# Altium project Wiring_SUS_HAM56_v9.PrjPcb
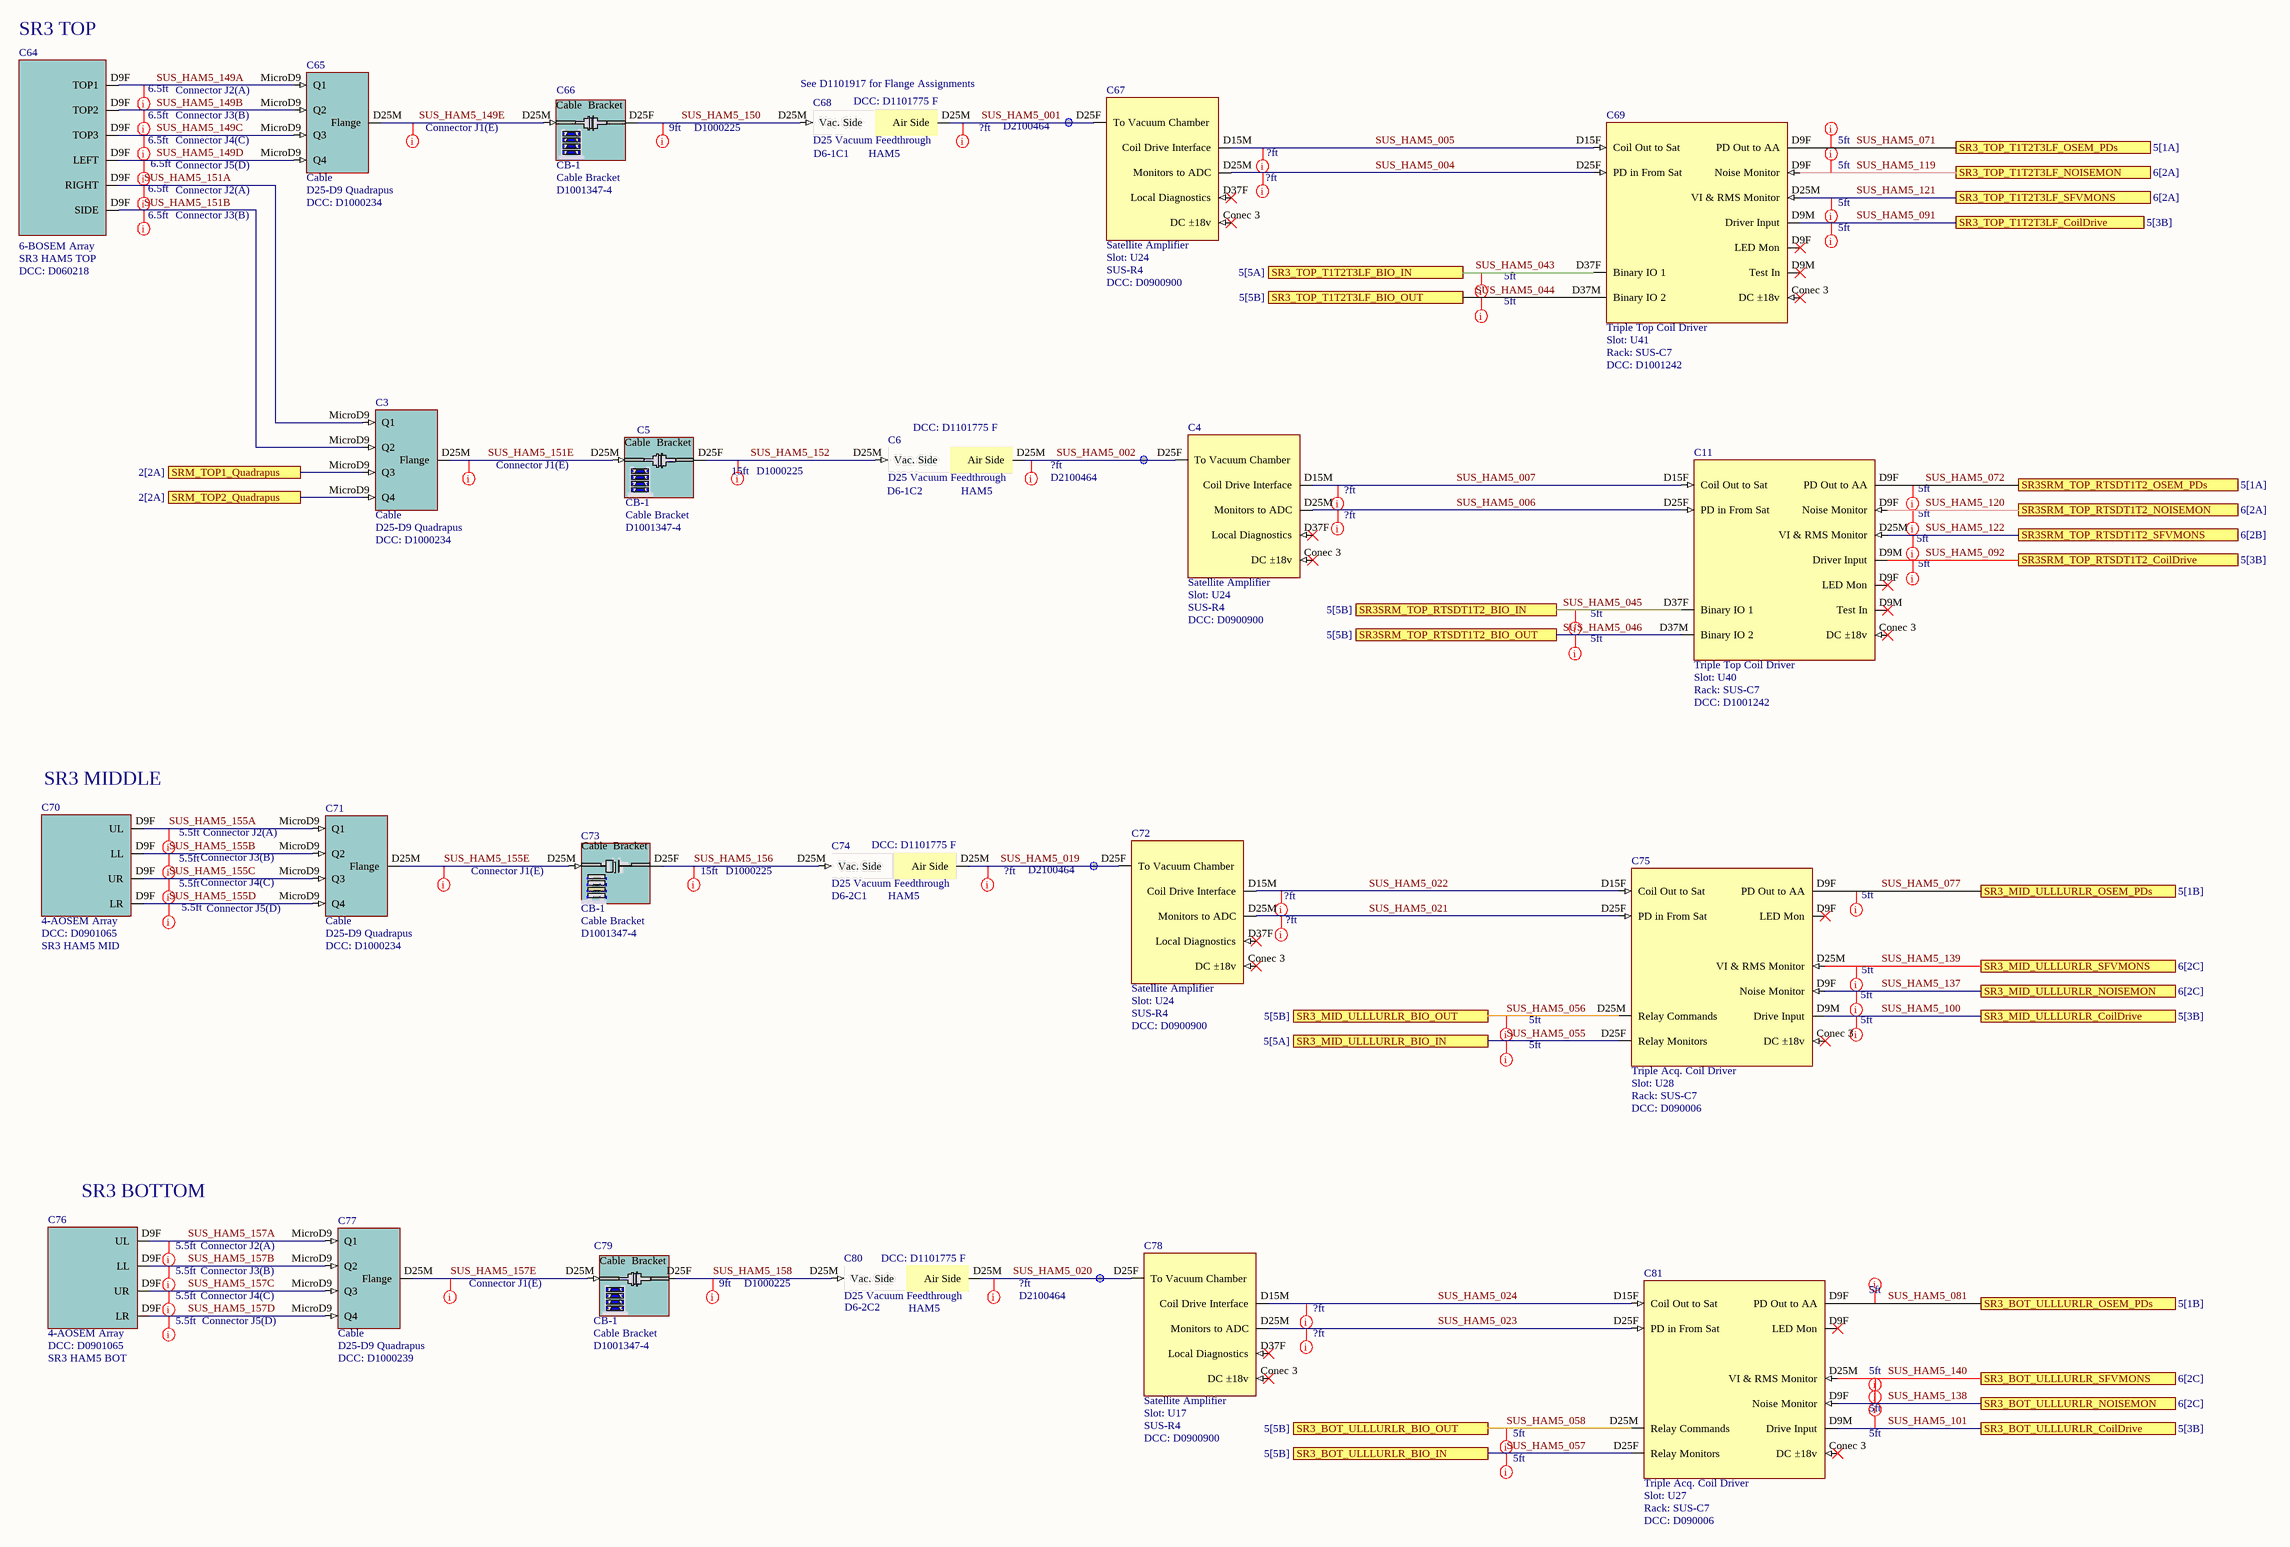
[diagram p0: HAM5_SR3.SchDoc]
8 sheets, 119 parts. Net scope: flat (ports and power ports of the same name join across sheets).
Sheets:
  HAM5_SR3.SchDoc
  HAM5_SRM.SchDoc
  HAM5_OFI_ZM6.SchDoc
  HAM6_OUT_SUS.SchDoc
  SUSH56_ADC_DAC.SchDoc
  SUSAUXH56_ADC_DAC.SchDoc
  RACK_SUS_R4.SchDoc
  RACK_SUS_C7_C8.SchDoc

## Sheet HAM5_SR3.SchDoc: HAM5 SR3 OSEMs to Drivers
size C; Engineer: L. Sanchez; Organization: LIGO Laboratory; Address1: California Institute of Technology; Address2: Massachusetts Institute of Technology; DocumentNumber: D1002740; Revision: v9; SheetNumber: 1; SheetTotal: 8

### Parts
C3  Cable  value D25-D9 Quadrapus  DCC: D1000234
C4  Satellite Amplifier  Slot: U24  Rack: SUS-R4  DCC: D0900900
C5  Slot: CB-1  DCC: D1001347-4  (hidden comment: Cable Bracket)
C6  D25 Vacuum Feedthrough  DCC: D1101775 F  Feedthrough: D6-1C2  Chamber: HAM5
C11  Triple Top Coil Driver  Slot: U40  Rack: SUS-C7  DCC: D1001242
C64  6-BOSEM Array  Parameter 1: SR3 HAM5 TOP  DCC: D060218
C65  Cable  value D25-D9 Quadrapus  DCC: D1000234
C66  Slot: CB-1  DCC: D1001347-4  (hidden comment: Cable Bracket)
C67  Satellite Amplifier  Slot: U24  Rack: SUS-R4  DCC: D0900900
C68  D25 Vacuum Feedthrough  DCC: D1101775 F  Feedthrough: D6-1C1  Chamber: HAM5
C69  Triple Top Coil Driver  Slot: U41  Rack: SUS-C7  DCC: D1001242
C70  4-AOSEM Array  DCC: D0901065  Parameter: SR3 HAM5 MID
C71  Cable  value D25-D9 Quadrapus  DCC: D1000234
C72  Satellite Amplifier  Slot: U24  Rack: SUS-R4  DCC: D0900900
C73  Slot: CB-1  DCC: D1001347-4  (hidden comment: Cable Bracket)
C74  D25 Vacuum Feedthrough  DCC: D1101775 F  Feedthrough: D6-2C1  Chamber: HAM5
C75  Triple Acq. Coil Driver  Slot: U28  Rack: SUS-C7  DCC: D090006
C76  4-AOSEM Array  DCC: D0901065  Parameter: SR3 HAM5 BOT
C77  Cable  value D25-D9 Quadrapus  DCC: D1000239
C78  Satellite Amplifier  Slot: U17  Rack: SUS-R4  DCC: D0900900
C79  Slot: CB-1  DCC: D1001347-4  (hidden comment: Cable Bracket)
C80  D25 Vacuum Feedthrough  DCC: D1101775 F  Feedthrough: D6-2C2  Chamber: HAM5
C81  Triple Acq. Coil Driver  Slot: U27  Rack: SUS-C7  DCC: D090006

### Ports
SR3_BOT_ULLLURLR_BIO_IN (see 5[5B]), SR3_BOT_ULLLURLR_BIO_OUT (see 5[5B]), SR3_BOT_ULLLURLR_CoilDrive (see 5[3B]), SR3_BOT_ULLLURLR_NOISEMON (see 6[2C]), SR3_BOT_ULLLURLR_OSEM_PDs (see 5[1B]), SR3_BOT_ULLLURLR_SFVMONS (see 6[2C]), SR3_MID_ULLLURLR_BIO_IN (see 5[5A]), SR3_MID_ULLLURLR_BIO_OUT (see 5[5B]), SR3_MID_ULLLURLR_CoilDrive (see 5[3B]), SR3_MID_ULLLURLR_NOISEMON (see 6[2C]), SR3_MID_ULLLURLR_OSEM_PDs (see 5[1B]), SR3_MID_ULLLURLR_SFVMONS (see 6[2C]), SR3_TOP_T1T2T3LF_BIO_IN (see 5[5A]), SR3_TOP_T1T2T3LF_BIO_OUT (see 5[5B]), SR3_TOP_T1T2T3LF_CoilDrive (see 5[3B]), SR3_TOP_T1T2T3LF_NOISEMON (see 6[2A]), SR3_TOP_T1T2T3LF_OSEM_PDs (see 5[1A]), SR3_TOP_T1T2T3LF_SFVMONS (see 6[2A]), SR3SRM_TOP_RTSDT1T2_BIO_IN (see 5[5B]), SR3SRM_TOP_RTSDT1T2_BIO_OUT (see 5[5B]), SR3SRM_TOP_RTSDT1T2_CoilDrive (see 5[3B]), SR3SRM_TOP_RTSDT1T2_NOISEMON (see 6[2A]), SR3SRM_TOP_RTSDT1T2_OSEM_PDs (see 5[1A]), SR3SRM_TOP_RTSDT1T2_SFVMONS (see 6[2B]), SRM_TOP1_Quadrapus (see 2[2A]), SRM_TOP2_Quadrapus (see 2[2A])

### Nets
SUS_HAM5_001: C67.D25F(To_Vacuum_Chamber) C68.D25M(Air_Side)
SUS_HAM5_002: C4.D25F(To_Vacuum_Chamber) C6.D25M(Air_Side)
SUS_HAM5_004: C67.D25M(Monitors_to_ADC) C69.D25F(PD_in_From_Sat)
SUS_HAM5_005: C67.D15M(Coil_Drive_Interface) C69.D15F(Coil_Out_to_Sat)
SUS_HAM5_006: C4.D25M(Monitors_to_ADC) C11.D25F(PD_in_From_Sat)
SUS_HAM5_007: C4.D15M(Coil_Drive_Interface) C11.D15F(Coil_Out_to_Sat)
SUS_HAM5_019: C72.D25F(To_Vacuum_Chamber) C74.D25M(Air_Side)
SUS_HAM5_020: C78.D25F(To_Vacuum_Chamber) C80.D25M(Air_Side)
SUS_HAM5_021: C72.D25M(Monitors_to_ADC) C75.D25F(PD_in_From_Sat)
SUS_HAM5_022: C72.D15M(Coil_Drive_Interface) C75.D15F(Coil_Out_to_Sat)
SUS_HAM5_023: C78.D25M(Monitors_to_ADC) C81.D25F(PD_in_From_Sat)
SUS_HAM5_024: C78.D15M(Coil_Drive_Interface) C81.D15F(Coil_Out_to_Sat)
SUS_HAM5_043: C69.D37F(Binary_IO_1) ; port SR3_TOP_T1T2T3LF_BIO_IN
SUS_HAM5_044: C69.D37M(Binary_IO_2) ; port SR3_TOP_T1T2T3LF_BIO_OUT
SUS_HAM5_045: C11.D37F(Binary_IO_1) ; port SR3SRM_TOP_RTSDT1T2_BIO_IN
SUS_HAM5_046: C11.D37M(Binary_IO_2) ; port SR3SRM_TOP_RTSDT1T2_BIO_OUT
SUS_HAM5_055: C75.D25F(Relay_Monitors) ; port SR3_MID_ULLLURLR_BIO_IN
SUS_HAM5_056: C75.D25M(Relay_Commands) ; port SR3_MID_ULLLURLR_BIO_OUT
SUS_HAM5_057: C81.D25F(Relay_Monitors) ; port SR3_BOT_ULLLURLR_BIO_IN
SUS_HAM5_058: C81.D25M(Relay_Commands) ; port SR3_BOT_ULLLURLR_BIO_OUT
SUS_HAM5_071: C69.D9F(PD_Out_to_AA) ; port SR3_TOP_T1T2T3LF_OSEM_PDs
SUS_HAM5_072: C11.D9F(PD_Out_to_AA) ; port SR3SRM_TOP_RTSDT1T2_OSEM_PDs
SUS_HAM5_077: C75.D9F(PD_Out_to_AA) ; port SR3_MID_ULLLURLR_OSEM_PDs
SUS_HAM5_081: C81.D9F(PD_Out_to_AA) ; port SR3_BOT_ULLLURLR_OSEM_PDs
SUS_HAM5_091: C69.D9M(Test_In) ; port SR3_TOP_T1T2T3LF_CoilDrive
SUS_HAM5_092: C11.D9M(Test_In) ; port SR3SRM_TOP_RTSDT1T2_CoilDrive
SUS_HAM5_100: C75.D9M(Drive_Input) ; port SR3_MID_ULLLURLR_CoilDrive
SUS_HAM5_101: C81.D9M(Drive_Input) ; port SR3_BOT_ULLLURLR_CoilDrive
SUS_HAM5_119: C69.D9F(Noise_Monitor) ; port SR3_TOP_T1T2T3LF_NOISEMON
SUS_HAM5_120: C11.D9F(Noise_Monitor) ; port SR3SRM_TOP_RTSDT1T2_NOISEMON
SUS_HAM5_121: C69.D25M(VI_&_RMS_Monitor) ; port SR3_TOP_T1T2T3LF_SFVMONS
SUS_HAM5_122: C11.D25M(VI_&_RMS_Monitor) ; port SR3SRM_TOP_RTSDT1T2_SFVMONS
SUS_HAM5_137: C75.D9F(Noise_Monitor) ; port SR3_MID_ULLLURLR_NOISEMON
SUS_HAM5_138: C81.D9F(Noise_Monitor) ; port SR3_BOT_ULLLURLR_NOISEMON
SUS_HAM5_139: C75.D25M(VI_&_RMS_Monitor) ; port SR3_MID_ULLLURLR_SFVMONS
SUS_HAM5_140: C81.D25M(VI_&_RMS_Monitor) ; port SR3_BOT_ULLLURLR_SFVMONS
SUS_HAM5_149A: C64.D9F(TOP1) C65.MicroD9(Q1)
SUS_HAM5_149B: C64.D9F(TOP2) C65.MicroD9(Q2)
SUS_HAM5_149C: C64.D9F(TOP3) C65.MicroD9(Q3)
SUS_HAM5_149D: C64.D9F(LEFT) C65.MicroD9(Q4)
SUS_HAM5_149E: C65.D25M(Flange) C66.D25M
SUS_HAM5_150: C66.D25F C68.D25M(Vac._Side)
SUS_HAM5_151A: C3.MicroD9(Q1) C64.D9F(RIGHT)
SUS_HAM5_151B: C3.MicroD9(Q2) C64.D9F(SIDE)
SUS_HAM5_151C: C3.MicroD9(Q3) ; port SRM_TOP1_Quadrapus
SUS_HAM5_151D: C3.MicroD9(Q4) ; port SRM_TOP2_Quadrapus
SUS_HAM5_151E: C3.D25M(Flange) C5.D25M
SUS_HAM5_152: C5.D25F C6.D25M(Vac._Side)
SUS_HAM5_155A: C70.D9F(UL) C71.MicroD9(Q1)
SUS_HAM5_155B: C70.D9F(LL) C71.MicroD9(Q2)
SUS_HAM5_155C: C70.D9F(UR) C71.MicroD9(Q3)
SUS_HAM5_155D: C70.D9F(LR) C71.MicroD9(Q4)
SUS_HAM5_155E: C71.D25M(Flange) C73.D25M
SUS_HAM5_156: C73.D25F C74.D25M(Vac._Side)
SUS_HAM5_157A: C76.D9F(UL) C77.MicroD9(Q1)
SUS_HAM5_157B: C76.D9F(LL) C77.MicroD9(Q2)
SUS_HAM5_157C: C76.D9F(UR) C77.MicroD9(Q3)
SUS_HAM5_157D: C76.D9F(LR) C77.MicroD9(Q4)
SUS_HAM5_157E: C77.D25M(Flange) C79.D25M
SUS_HAM5_158: C79.D25F C80.D25M(Vac._Side)

Not connected (* = marked no-connect by the designer): C4 Conec 3(DC_±18v)* D37F(Local_Diagnostics)*; C11 Conec 3(DC_±18v)*; C67 Conec 3(DC_±18v)* D37F(Local_Diagnostics)*; C69 Conec 3(DC_±18v)*; C72 Conec 3(DC_±18v)* D37F(Local_Diagnostics)*; C75 Conec 3(DC_±18v)*; C78 Conec 3(DC_±18v)* D37F(Local_Diagnostics)*; C81 Conec 3(DC_±18v)*

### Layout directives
Length: 5ft; DCC: Dxxxxxxx: SUS_HAM5_043, SUS_HAM5_044, SUS_HAM5_045, SUS_HAM5_046, SUS_HAM5_055, SUS_HAM5_056, SUS_HAM5_057, SUS_HAM5_058, SUS_HAM5_071, SUS_HAM5_072, SUS_HAM5_077, SUS_HAM5_081, SUS_HAM5_091, SUS_HAM5_092, SUS_HAM5_100, SUS_HAM5_101, SUS_HAM5_119, SUS_HAM5_120, SUS_HAM5_121, SUS_HAM5_122, SUS_HAM5_137, SUS_HAM5_138, SUS_HAM5_139, SUS_HAM5_140
Length: ?ft; DCC: Dxxxxxxx: SUS_HAM5_004, SUS_HAM5_005, SUS_HAM5_006, SUS_HAM5_007, SUS_HAM5_021, SUS_HAM5_022, SUS_HAM5_023, SUS_HAM5_024
Length: 6.5ft; DCC: Connector J1(E): SUS_HAM5_149E, SUS_HAM5_151E
Length: 15ft; DCC: D1000225: SUS_HAM5_152, SUS_HAM5_156
Length: ?ft; DCC: D2100464: SUS_HAM5_001, SUS_HAM5_002, SUS_HAM5_019, SUS_HAM5_020
Length: 6.5ft; DCC: Connector J2(A): SUS_HAM5_149A, SUS_HAM5_151A
Length: 6.5ft; DCC: Connector J3(B): SUS_HAM5_149B, SUS_HAM5_151B
Length: 9ft; DCC: D1000225: SUS_HAM5_150, SUS_HAM5_158
Length: 6.5ft; DCC: Connector J4(C): SUS_HAM5_149C
Length: 6.5ft; DCC: Connector J5(D): SUS_HAM5_149D
Length: 5ft; DCC: Connector J1(E): SUS_HAM5_157E
Length: 5.5ft; DCC: Connector J1(E): SUS_HAM5_155E
Length: 5.5ft; DCC: Connector J2(A): SUS_HAM5_155A, SUS_HAM5_157A
Length: 5.5ft; DCC: Connector J3(B): SUS_HAM5_155B, SUS_HAM5_157B
Length: 5.5ft; DCC: Connector J4(C): SUS_HAM5_155C, SUS_HAM5_157C
Length: 5.5ft; DCC: Connector J5(D): SUS_HAM5_155D, SUS_HAM5_157D

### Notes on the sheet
- (near C64) SR3 TOP
- (near C68) See D1101917 for Flange Assignments
- (near C70) SR3 MIDDLE
- (near C76) SR3 BOTTOM

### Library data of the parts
C3 C65 C71 C77 = Flange: Rack: SUS-R?; Serial: Sxxxxxxx; Slot: U?; System: SUS
C4 C67 C72 C78 = Satellite Amplifier: System: SUS; Serial: Sxxxxxxx
C5 = Cable Bracket 4 1-4: Rack: SUS-R?; Serial: Sxxxxxxx; System: SUS
C6 C68 C74 C80 = VacFeedD25: Serial: Sxxxxxxx; System: ISC; Rack: R?; Slot: U?
C11 C69 = Triple Top CD: System: SUS; Serial: Sxxxxxxx
C64 = 6-BOSEM Array HAM: Serial: Sxxxxxxx; System: SUS; Slot: U?; Rack: SUS-R?
C66 = Cable Bracket 3 1-4: Rack: SUS-R?; Serial: Sxxxxxxx; System: SUS
C70 C76 = 4-BOSEM Array: Rack: SUS-R?; Serial: Sxxxxxxx; Slot: U?; System: SUS
C73 = Cable Bracket 2 1-4: Rack: SUS-R?; Serial: Sxxxxxxx; System: SUS
C75 C81 = Triple Acquisition Coil Driver: System: SUS; Serial: Sxxxxxxx
C79 = Cable Bracket 1 1-4: Rack: SUS-R?; Serial: Sxxxxxxx; System: SUS

## Sheet HAM5_SRM.SchDoc: HAM5 SRM OSEMs to Drivers
size C; Engineer: L. Sanchez; Organization: LIGO Laboratory; Address1: California Institute of Technology; Address2: Massachusetts Institute of Technology; DocumentNumber: D1002740; Revision: v9; SheetNumber: 2; SheetTotal: 8
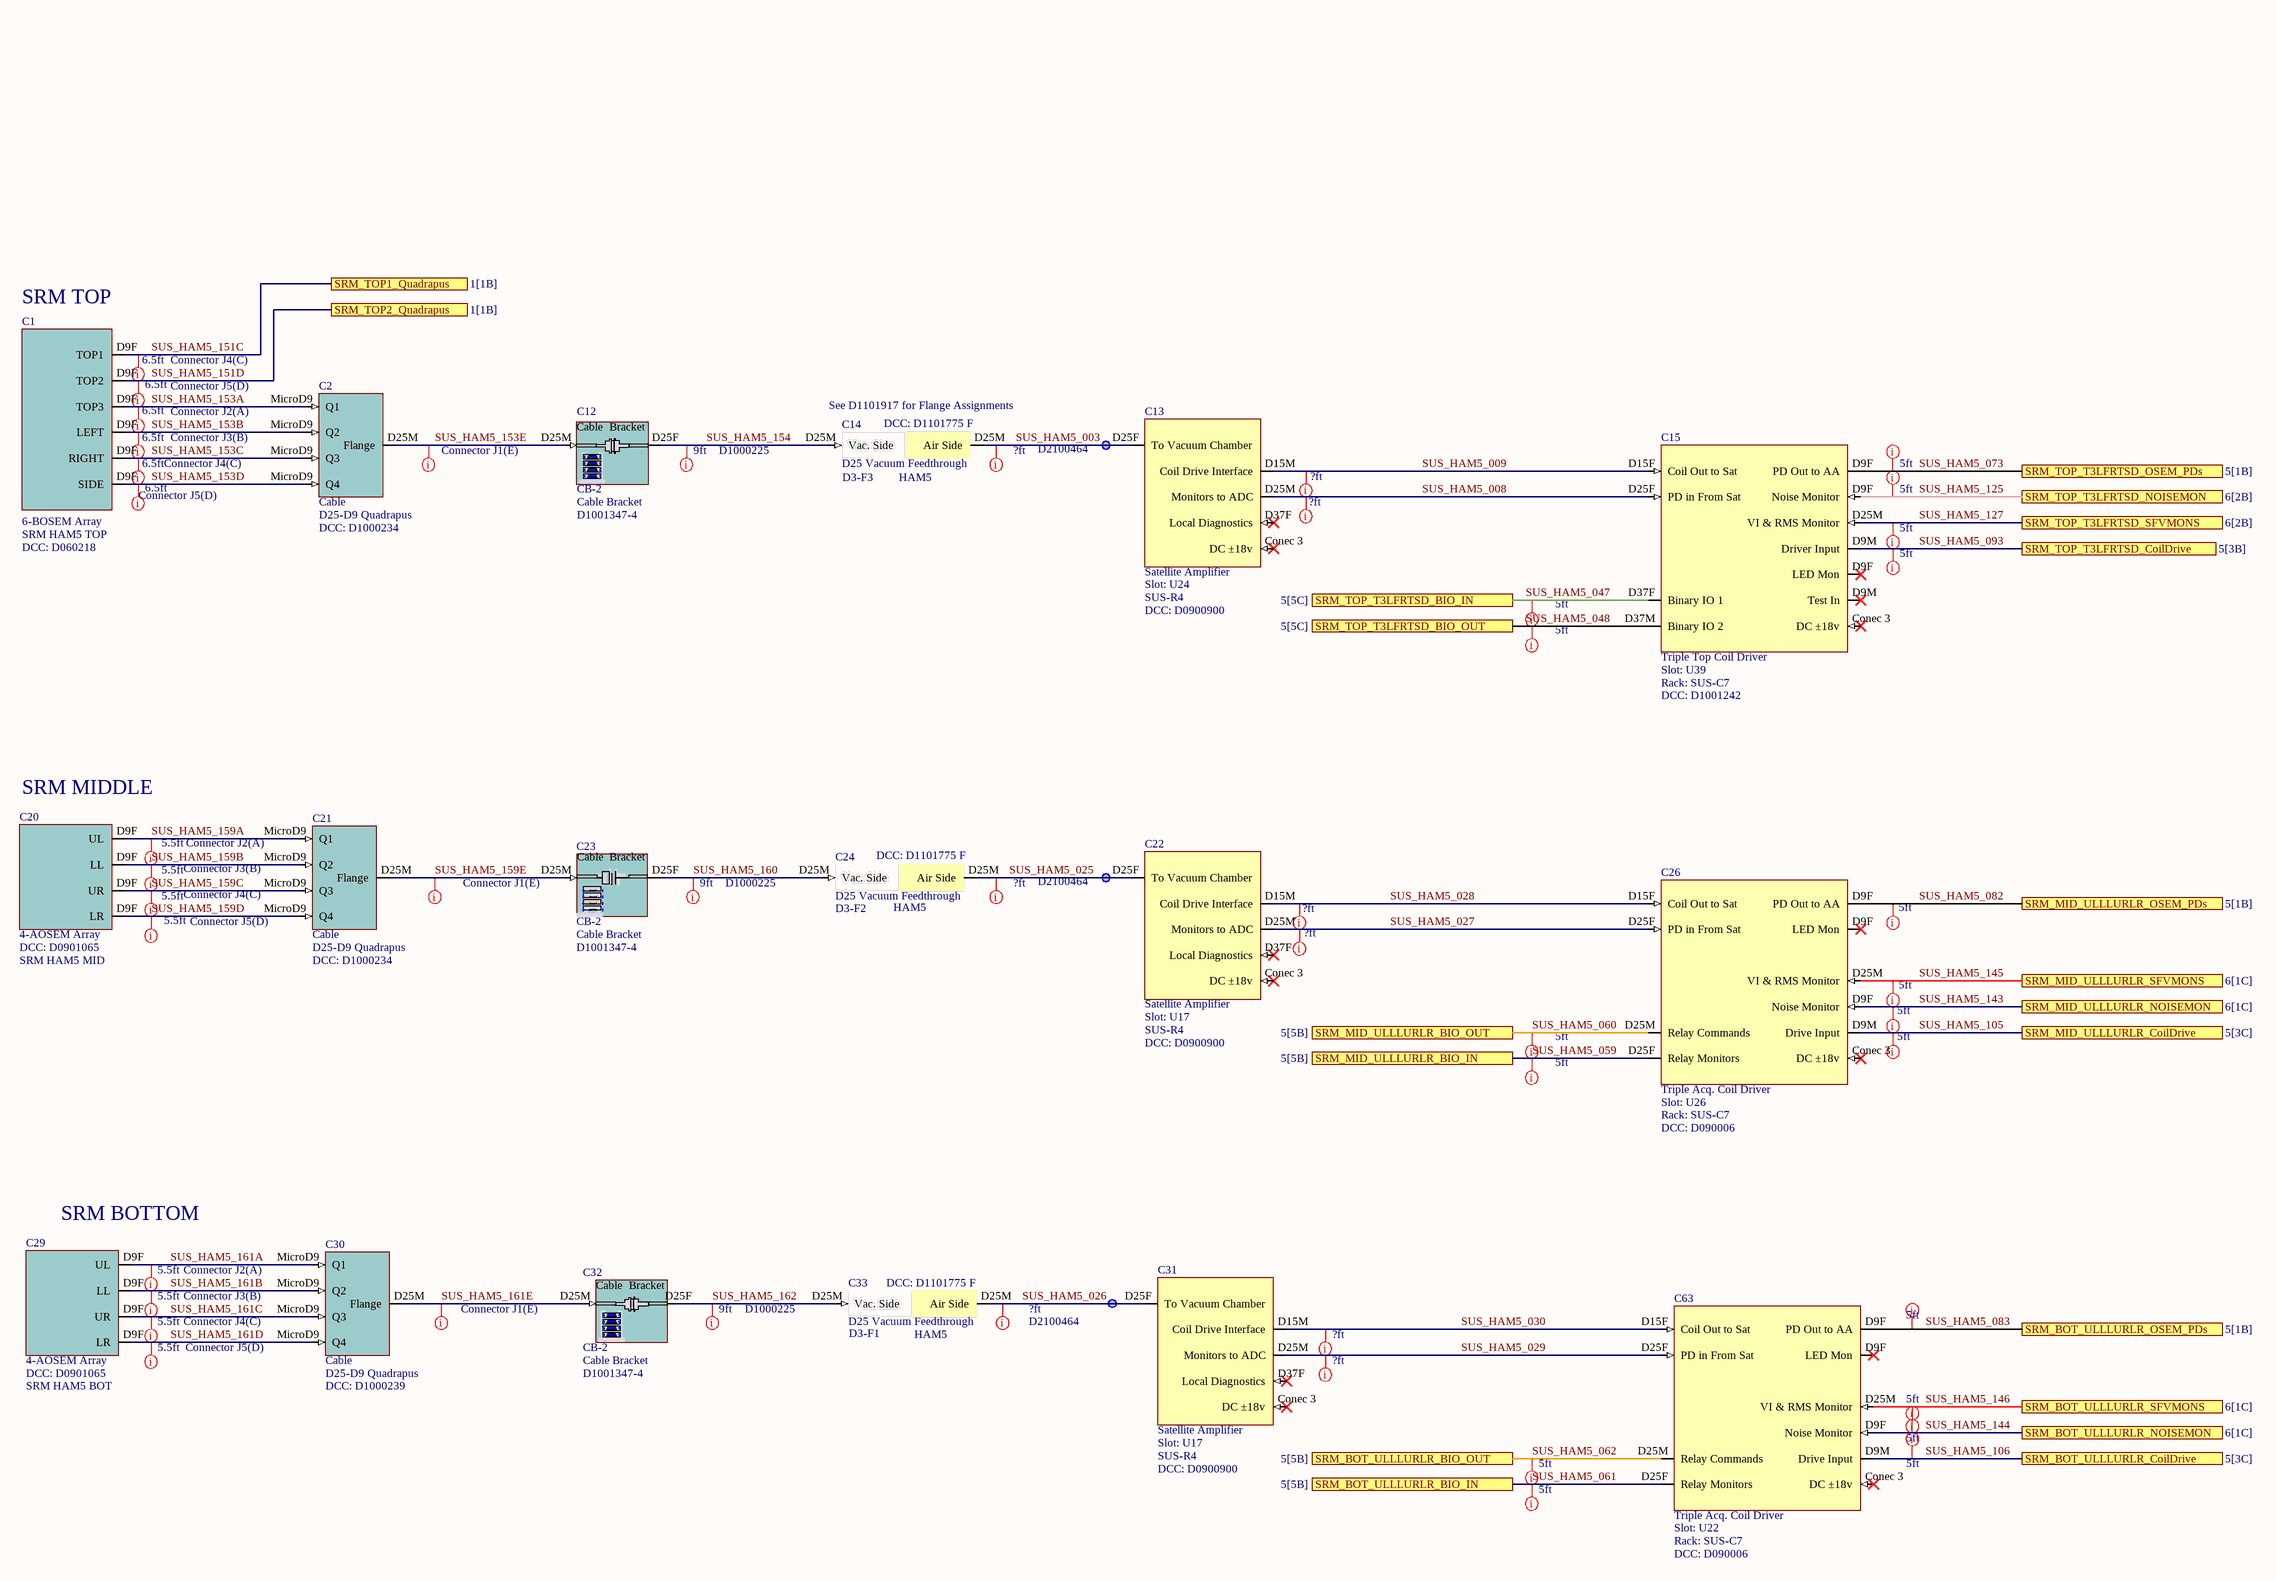
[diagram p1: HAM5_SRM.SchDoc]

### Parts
C1  6-BOSEM Array  Parameter 1: SRM HAM5 TOP  DCC: D060218
C2  Cable  value D25-D9 Quadrapus  DCC: D1000234
C12  Slot: CB-2  DCC: D1001347-4  (hidden comment: Cable Bracket)
C13  Satellite Amplifier  Slot: U24  Rack: SUS-R4  DCC: D0900900
C14  D25 Vacuum Feedthrough  DCC: D1101775 F  Feedthrough: D3-F3  Chamber: HAM5
C15  Triple Top Coil Driver  Slot: U39  Rack: SUS-C7  DCC: D1001242
C20  4-AOSEM Array  DCC: D0901065  Parameter: SRM HAM5 MID
C21  Cable  value D25-D9 Quadrapus  DCC: D1000234
C22  Satellite Amplifier  Slot: U17  Rack: SUS-R4  DCC: D0900900
C23  Slot: CB-2  DCC: D1001347-4  (hidden comment: Cable Bracket)
C24  D25 Vacuum Feedthrough  DCC: D1101775 F  Feedthrough: D3-F2  Chamber: HAM5
C26  Triple Acq. Coil Driver  Slot: U26  Rack: SUS-C7  DCC: D090006
C29  4-AOSEM Array  DCC: D0901065  Parameter: SRM HAM5 BOT
C30  Cable  value D25-D9 Quadrapus  DCC: D1000239
C31  Satellite Amplifier  Slot: U17  Rack: SUS-R4  DCC: D0900900
C32  Slot: CB-2  DCC: D1001347-4  (hidden comment: Cable Bracket)
C33  D25 Vacuum Feedthrough  DCC: D1101775 F  Feedthrough: D3-F1  Chamber: HAM5
C63  Triple Acq. Coil Driver  Slot: U22  Rack: SUS-C7  DCC: D090006

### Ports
SRM_BOT_ULLLURLR_BIO_IN (see 5[5B]), SRM_BOT_ULLLURLR_BIO_OUT (see 5[5B]), SRM_BOT_ULLLURLR_CoilDrive (see 5[3C]), SRM_BOT_ULLLURLR_NOISEMON (see 6[1C]), SRM_BOT_ULLLURLR_OSEM_PDs (see 5[1B]), SRM_BOT_ULLLURLR_SFVMONS (see 6[1C]), SRM_MID_ULLLURLR_BIO_IN (see 5[5B]), SRM_MID_ULLLURLR_BIO_OUT (see 5[5B]), SRM_MID_ULLLURLR_CoilDrive (see 5[3C]), SRM_MID_ULLLURLR_NOISEMON (see 6[1C]), SRM_MID_ULLLURLR_OSEM_PDs (see 5[1B]), SRM_MID_ULLLURLR_SFVMONS (see 6[1C]), SRM_TOP1_Quadrapus (see 1[1B]), SRM_TOP2_Quadrapus (see 1[1B]), SRM_TOP_T3LFRTSD_BIO_IN (see 5[5C]), SRM_TOP_T3LFRTSD_BIO_OUT (see 5[5C]), SRM_TOP_T3LFRTSD_CoilDrive (see 5[3B]), SRM_TOP_T3LFRTSD_NOISEMON (see 6[2B]), SRM_TOP_T3LFRTSD_OSEM_PDs (see 5[1B]), SRM_TOP_T3LFRTSD_SFVMONS (see 6[2B])

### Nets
SUS_HAM5_003: C13.D25F(To_Vacuum_Chamber) C14.D25M(Air_Side)
SUS_HAM5_008: C13.D25M(Monitors_to_ADC) C15.D25F(PD_in_From_Sat)
SUS_HAM5_009: C13.D15M(Coil_Drive_Interface) C15.D15F(Coil_Out_to_Sat)
SUS_HAM5_025: C22.D25F(To_Vacuum_Chamber) C24.D25M(Air_Side)
SUS_HAM5_026: C31.D25F(To_Vacuum_Chamber) C33.D25M(Air_Side)
SUS_HAM5_027: C22.D25M(Monitors_to_ADC) C26.D25F(PD_in_From_Sat)
SUS_HAM5_028: C22.D15M(Coil_Drive_Interface) C26.D15F(Coil_Out_to_Sat)
SUS_HAM5_029: C31.D25M(Monitors_to_ADC) C63.D25F(PD_in_From_Sat)
SUS_HAM5_030: C31.D15M(Coil_Drive_Interface) C63.D15F(Coil_Out_to_Sat)
SUS_HAM5_047: C15.D37F(Binary_IO_1) ; port SRM_TOP_T3LFRTSD_BIO_IN
SUS_HAM5_048: C15.D37M(Binary_IO_2) ; port SRM_TOP_T3LFRTSD_BIO_OUT
SUS_HAM5_059: C26.D25F(Relay_Monitors) ; port SRM_MID_ULLLURLR_BIO_IN
SUS_HAM5_060: C26.D25M(Relay_Commands) ; port SRM_MID_ULLLURLR_BIO_OUT
SUS_HAM5_061: C63.D25F(Relay_Monitors) ; port SRM_BOT_ULLLURLR_BIO_IN
SUS_HAM5_062: C63.D25M(Relay_Commands) ; port SRM_BOT_ULLLURLR_BIO_OUT
SUS_HAM5_073: C15.D9F(PD_Out_to_AA) ; port SRM_TOP_T3LFRTSD_OSEM_PDs
SUS_HAM5_082: C26.D9F(PD_Out_to_AA) ; port SRM_MID_ULLLURLR_OSEM_PDs
SUS_HAM5_083: C63.D9F(PD_Out_to_AA) ; port SRM_BOT_ULLLURLR_OSEM_PDs
SUS_HAM5_093: C15.D9M(Test_In) ; port SRM_TOP_T3LFRTSD_CoilDrive
SUS_HAM5_105: C26.D9M(Drive_Input) ; port SRM_MID_ULLLURLR_CoilDrive
SUS_HAM5_106: C63.D9M(Drive_Input) ; port SRM_BOT_ULLLURLR_CoilDrive
SUS_HAM5_125: C15.D9F(Noise_Monitor) ; port SRM_TOP_T3LFRTSD_NOISEMON
SUS_HAM5_127: C15.D25M(VI_&_RMS_Monitor) ; port SRM_TOP_T3LFRTSD_SFVMONS
SUS_HAM5_143: C26.D9F(Noise_Monitor) ; port SRM_MID_ULLLURLR_NOISEMON
SUS_HAM5_144: C63.D9F(Noise_Monitor) ; port SRM_BOT_ULLLURLR_NOISEMON
SUS_HAM5_145: C26.D25M(VI_&_RMS_Monitor) ; port SRM_MID_ULLLURLR_SFVMONS
SUS_HAM5_146: C63.D25M(VI_&_RMS_Monitor) ; port SRM_BOT_ULLLURLR_SFVMONS
SUS_HAM5_151C: C1.D9F(TOP1) ; port SRM_TOP1_Quadrapus
SUS_HAM5_151D: C1.D9F(TOP2) ; port SRM_TOP2_Quadrapus
SUS_HAM5_153A: C1.D9F(TOP3) C2.MicroD9(Q1)
SUS_HAM5_153B: C1.D9F(LEFT) C2.MicroD9(Q2)
SUS_HAM5_153C: C1.D9F(RIGHT) C2.MicroD9(Q3)
SUS_HAM5_153D: C1.D9F(SIDE) C2.MicroD9(Q4)
SUS_HAM5_153E: C2.D25M(Flange) C12.D25M
SUS_HAM5_154: C12.D25F C14.D25M(Vac._Side)
SUS_HAM5_159A: C20.D9F(UL) C21.MicroD9(Q1)
SUS_HAM5_159B: C20.D9F(LL) C21.MicroD9(Q2)
SUS_HAM5_159C: C20.D9F(UR) C21.MicroD9(Q3)
SUS_HAM5_159D: C20.D9F(LR) C21.MicroD9(Q4)
SUS_HAM5_159E: C21.D25M(Flange) C23.D25M
SUS_HAM5_160: C23.D25F C24.D25M(Vac._Side)
SUS_HAM5_161A: C29.D9F(UL) C30.MicroD9(Q1)
SUS_HAM5_161B: C29.D9F(LL) C30.MicroD9(Q2)
SUS_HAM5_161C: C29.D9F(UR) C30.MicroD9(Q3)
SUS_HAM5_161D: C29.D9F(LR) C30.MicroD9(Q4)
SUS_HAM5_161E: C30.D25M(Flange) C32.D25M
SUS_HAM5_162: C32.D25F C33.D25M(Vac._Side)

Not connected (* = marked no-connect by the designer): C13 Conec 3(DC_±18v)* D37F(Local_Diagnostics)*; C15 Conec 3(DC_±18v)*; C22 Conec 3(DC_±18v)* D37F(Local_Diagnostics)*; C26 Conec 3(DC_±18v)*; C31 Conec 3(DC_±18v)* D37F(Local_Diagnostics)*; C63 Conec 3(DC_±18v)*

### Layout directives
Length: 5ft; DCC: Connector J1(E): SUS_HAM5_161E
Length: 5.5ft; DCC: Connector J1(E): SUS_HAM5_159E
Length: 6.5ft; DCC: Connector J1(E): SUS_HAM5_153E
Length: 5ft; DCC: Dxxxxxxx: SUS_HAM5_047, SUS_HAM5_048, SUS_HAM5_059, SUS_HAM5_060, SUS_HAM5_061, SUS_HAM5_062, SUS_HAM5_073, SUS_HAM5_082, SUS_HAM5_083, SUS_HAM5_093, SUS_HAM5_105, SUS_HAM5_106, SUS_HAM5_125, SUS_HAM5_127, SUS_HAM5_143, SUS_HAM5_144, SUS_HAM5_145, SUS_HAM5_146
Length: ?ft; DCC: Dxxxxxxx: SUS_HAM5_008, SUS_HAM5_009, SUS_HAM5_027, SUS_HAM5_028, SUS_HAM5_029, SUS_HAM5_030
Length: 6.5ft; DCC: Connector J2(A): SUS_HAM5_153A
Length: 6.5ft; DCC: Connector J3(B): SUS_HAM5_153B
Length: 6.5ft; DCC: Connector J4(C): SUS_HAM5_151C, SUS_HAM5_153C
Length: 6.5ft; DCC: Connector J5(D): SUS_HAM5_151D, SUS_HAM5_153D
Length: 5.5ft; DCC: Connector J2(A): SUS_HAM5_159A, SUS_HAM5_161A
Length: 5.5ft; DCC: Connector J3(B): SUS_HAM5_159B, SUS_HAM5_161B
Length: 5.5ft; DCC: Connector J4(C): SUS_HAM5_159C, SUS_HAM5_161C
Length: 5.5ft; DCC: Connector J5(D): SUS_HAM5_159D, SUS_HAM5_161D
Length: 9ft; DCC: D1000225: SUS_HAM5_154, SUS_HAM5_160, SUS_HAM5_162
Length: ?ft; DCC: D2100464: SUS_HAM5_003, SUS_HAM5_025, SUS_HAM5_026

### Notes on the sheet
- (near C1) SRM TOP
- (near C14) See D1101917 for Flange Assignments
- (near C20) SRM MIDDLE
- (near C29) SRM BOTTOM

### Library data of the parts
C1 = 6-BOSEM Array HAM: as C64 on sheet HAM5_SR3
C2 C21 C30 = Flange: as C3 on sheet HAM5_SR3
C12 = Cable Bracket 3 1-4: as C66 on sheet HAM5_SR3
C13 C22 C31 = Satellite Amplifier: System: SUS; Serial: Sxxxxxxx
C14 C24 C33 = VacFeedD25: as C6 on sheet HAM5_SR3
C15 = Triple Top CD: System: SUS; Serial: Sxxxxxxx
C20 C29 = 4-BOSEM Array: as C70 on sheet HAM5_SR3
C23 = Cable Bracket 2 1-4: as C73 on sheet HAM5_SR3
C26 C63 = Triple Acquisition Coil Driver: System: SUS; Serial: Sxxxxxxx
C32 = Cable Bracket 1 1-4: as C79 on sheet HAM5_SR3

## Sheet HAM5_OFI_ZM6.SchDoc: HAM5 OFI & ZM6 OSEMs to Drivers
size C; Engineer: L. Sanchez; Organization: LIGO Laboratory; Address1: California Institute of Technology; Address2: Massachusetts Institute of Technology; DocumentNumber: D1002740; Revision: v9; SheetNumber: 3; SheetTotal: 8
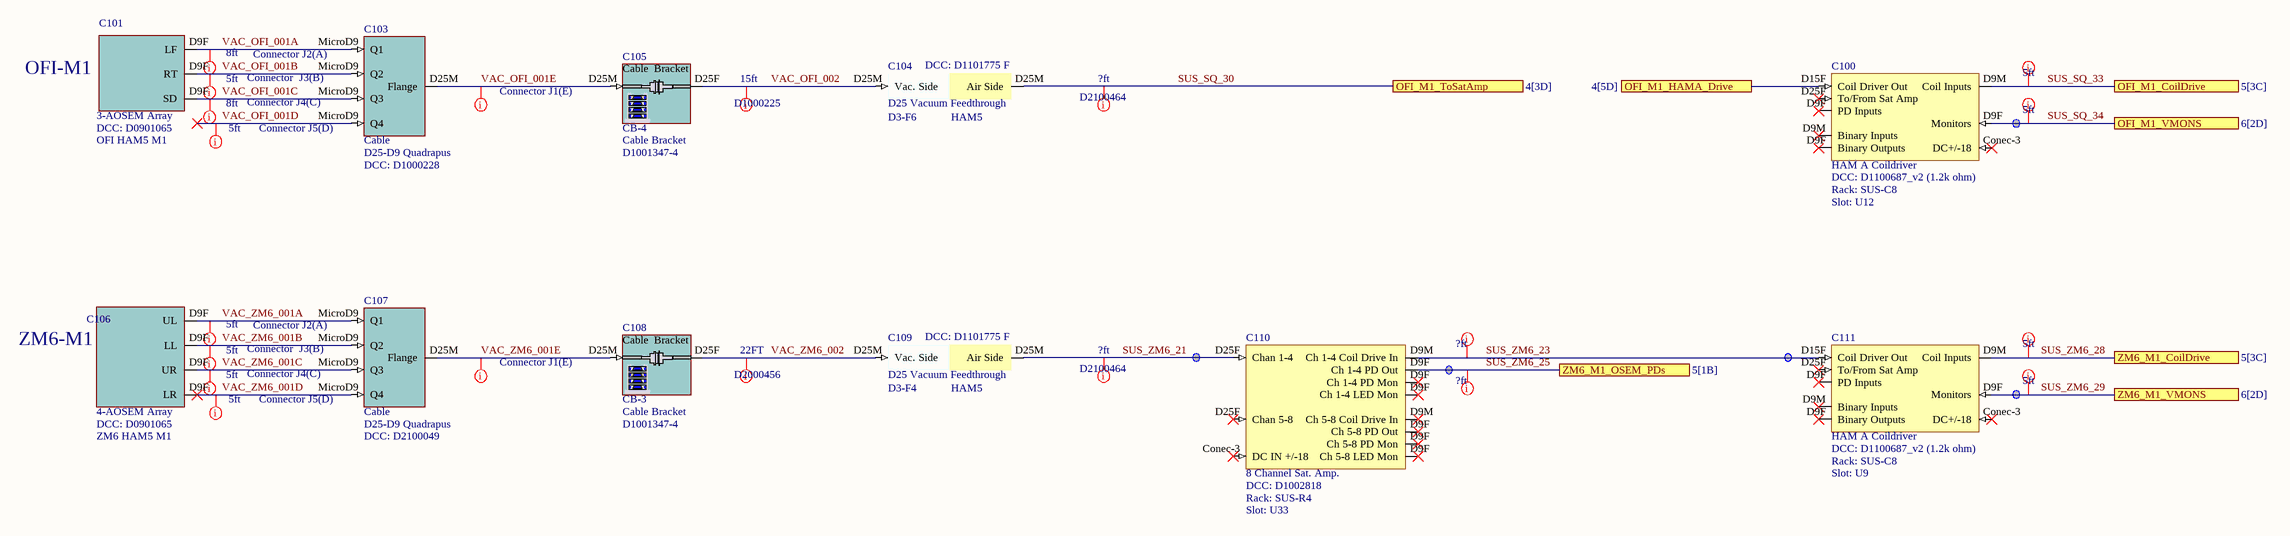
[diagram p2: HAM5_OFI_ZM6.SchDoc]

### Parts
C100  HAM A Coildriver  DCC: D1100687_v2 (1.2k ohm)  Rack: SUS-C8  Slot: U12
C101  3-AOSEM Array  DCC: D0901065  Parameter: OFI HAM5 M1
C103  Cable  value D25-D9 Quadrapus  DCC: D1000228
C104  D25 Vacuum Feedthrough  DCC: D1101775 F  Feedthrough: D3-F6  Chamber: HAM5
C105  Slot: CB-4  DCC: D1001347-4  (hidden comment: Cable Bracket)
C106  4-AOSEM Array  DCC: D0901065  Parameter: ZM6 HAM5 M1
C107  Cable  value D25-D9 Quadrapus  DCC: D2100049
C108  Slot: CB-3  DCC: D1001347-4  (hidden comment: Cable Bracket)
C109  D25 Vacuum Feedthrough  DCC: D1101775 F  Feedthrough: D3-F4  Chamber: HAM5
C110  8 Channel Sat. Amp.  DCC: D1002818  Rack: SUS-R4  Slot: U33
C111  HAM A Coildriver  DCC: D1100687_v2 (1.2k ohm)  Rack: SUS-C8  Slot: U9

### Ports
OFI_M1_CoilDrive (see 5[3C]), OFI_M1_HAMA_Drive (see 4[5D]), OFI_M1_ToSatAmp (see 4[3D]), OFI_M1_VMONS (see 6[2D]), ZM6_M1_CoilDrive (see 5[3C]), ZM6_M1_OSEM_PDs (see 5[1B]), ZM6_M1_VMONS (see 6[2D])

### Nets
SUS_SQ_30: C104.D25M(Air_Side) ; port OFI_M1_ToSatAmp
SUS_SQ_031: C100.D15F(Coil_Driver_Out) ; port OFI_M1_HAMA_Drive
SUS_SQ_33: C100.D9M(Coil_Inputs) ; port OFI_M1_CoilDrive
SUS_SQ_34: C100.D9F(PD_Inputs) ; port OFI_M1_VMONS
SUS_ZM6_21: C109.D25M(Air_Side) C110.D25F(Chan_1-4)
SUS_ZM6_23: C110.D9M(Ch_1-4_Coil_Drive_In) C111.D15F(Coil_Driver_Out)
SUS_ZM6_25: C110.D9F(Ch_1-4_PD_Out) ; port ZM6_M1_OSEM_PDs
SUS_ZM6_28: C111.D9M(Coil_Inputs) ; port ZM6_M1_CoilDrive
SUS_ZM6_29: C111.D9F(PD_Inputs) ; port ZM6_M1_VMONS
VAC_OFI_001A: C101.D9F(LF) C103.MicroD9(Q1)
VAC_OFI_001B: C101.D9F(RT) C103.MicroD9(Q2)
VAC_OFI_001C: C101.D9F(SD) C103.MicroD9(Q3)
VAC_OFI_001D: C103.MicroD9(Q4)
VAC_OFI_001E: C103.D25M(Flange) C105.D25M
VAC_OFI_002: C104.D25M(Vac._Side) C105.D25F
VAC_ZM6_001A: C106.D9F(UL) C107.MicroD9(Q1)
VAC_ZM6_001B: C106.D9F(LL) C107.MicroD9(Q2)
VAC_ZM6_001C: C106.D9F(UR) C107.MicroD9(Q3)
VAC_ZM6_001D: C106.D9F(LR) C107.MicroD9(Q4)
VAC_ZM6_001E: C107.D25M(Flange) C108.D25M
VAC_ZM6_002: C108.D25F C109.D25M(Vac._Side)

Not connected (* = marked no-connect by the designer): C100 Conec-3(DC+/-18)* D25F(To/From_Sat_Amp)*; C110 Conec-3(DC_IN_+/-18)*; C111 Conec-3(DC+/-18)* D25F(To/From_Sat_Amp)*

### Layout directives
Length: ?ft; DCC: D2100464: SUS_SQ_30, SUS_ZM6_21
Length: 15ft; DCC: D1000225: VAC_OFI_002
Length: 5ft; DCC: Connector J5(D): VAC_OFI_001D, VAC_ZM6_001D
Length: 8ft; DCC: Connector J2(A): VAC_OFI_001A
Length: 5ft; DCC: Connector  J3(B): VAC_OFI_001B, VAC_ZM6_001B
Length: 8ft; DCC: Connector J4(C): VAC_OFI_001C
Length: 5ft; DCC: Dxxxxxxx: SUS_SQ_33, SUS_SQ_34, SUS_ZM6_28, SUS_ZM6_29
Length: 5ft; DCC: Connector J1(E): VAC_OFI_001E, VAC_ZM6_001E
Length: 22FT; DCC: D2000456: VAC_ZM6_002
Length: 5ft; DCC: Connector J2(A): VAC_ZM6_001A
Length: 5ft; DCC: Connector J4(C): VAC_ZM6_001C
Length: ?ft; DCC: -: SUS_ZM6_23, SUS_ZM6_25

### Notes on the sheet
- OFI-M1
- ZM6-M1

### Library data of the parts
C100 C111 = HAM A Coildriver: Serial: Sxxxxxxx; System: ISC
C101 = 3-AOSEM Array: Rack: SUS-R?; Serial: Sxxxxxxx; Slot: U?; System: SUS
C103 C107 = Flange: as C3 on sheet HAM5_SR3
C104 C109 = VacFeedD25: as C6 on sheet HAM5_SR3
C105 = Cable Bracket 4 1-4: as C5 on sheet HAM5_SR3
C106 = 4-BOSEM Array: as C70 on sheet HAM5_SR3
C108 = Cable Bracket 3 1-4: as C66 on sheet HAM5_SR3
C110 = 8 Channel Sat. Amp.: Serial: Sxxxxxxx; System: ISC

## Sheet HAM6_OUT_SUS.SchDoc: HAM6 OMC & OMs OSEMs to Drivers
size C; Engineer: L. Sanchez; Organization: LIGO Laboratory; Address1: California Institute of Technology; Address2: Massachusetts Institute of Technology; DocumentNumber: D1002740; Revision: v9; SheetNumber: 4; SheetTotal: 8
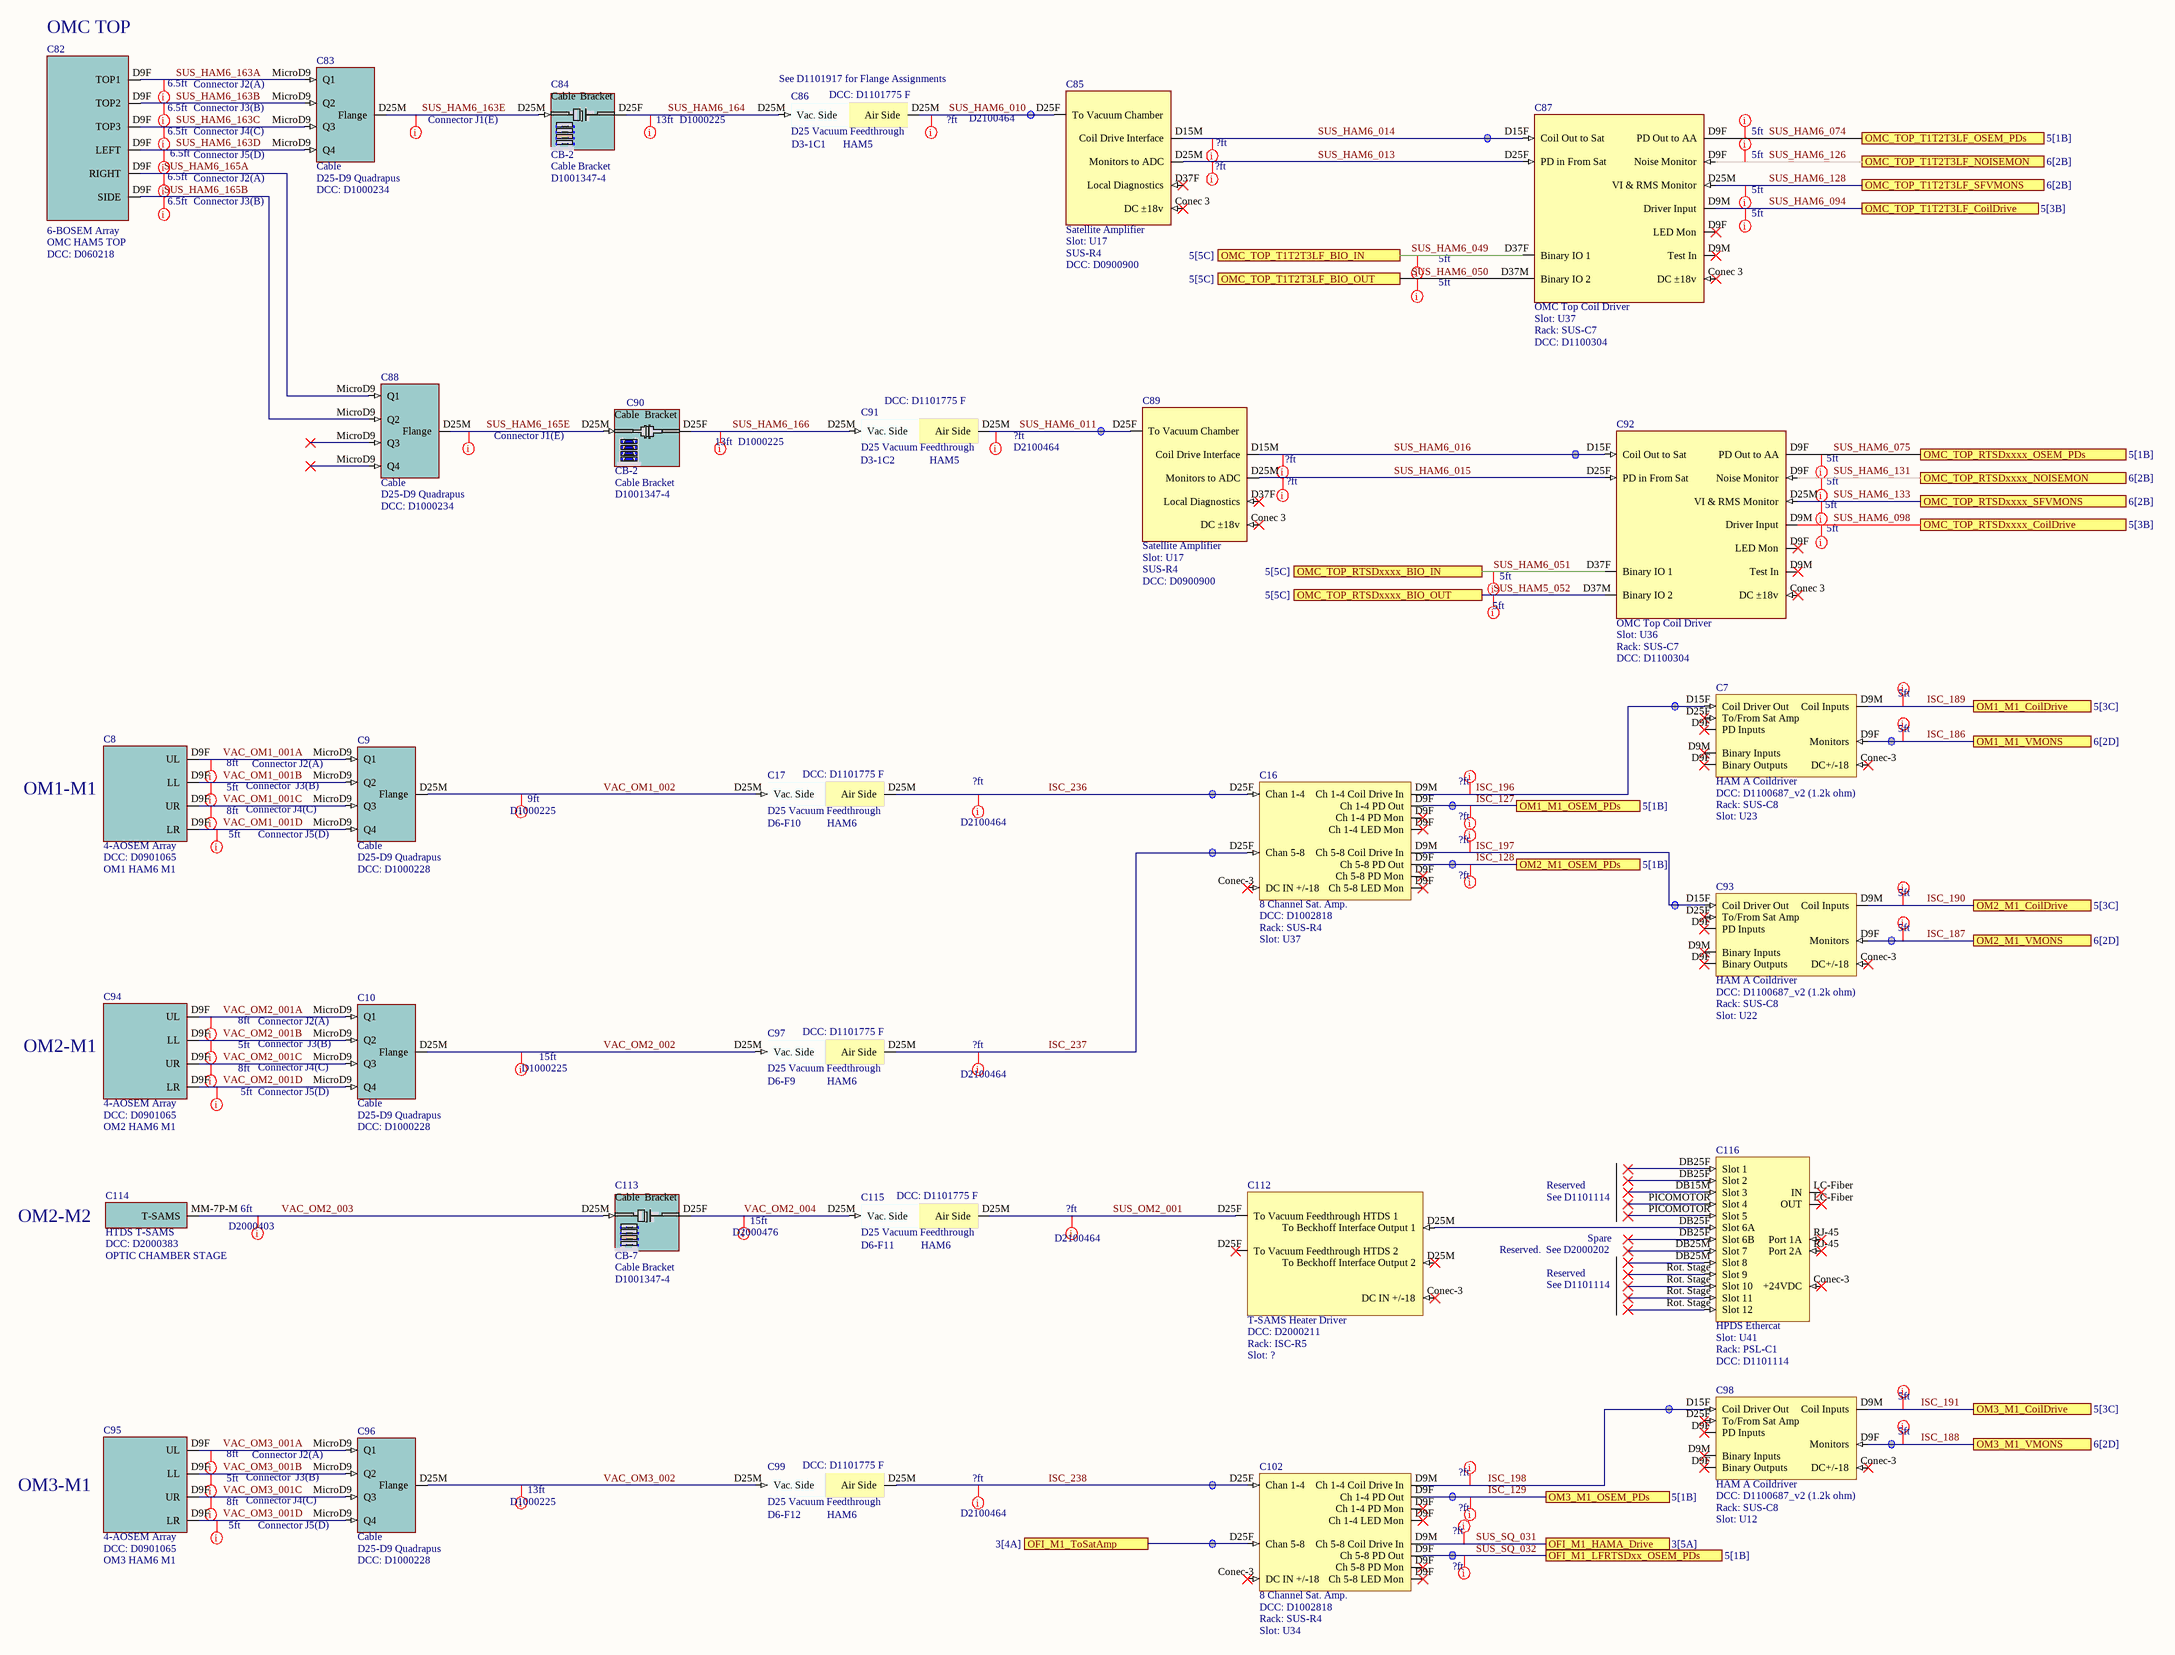
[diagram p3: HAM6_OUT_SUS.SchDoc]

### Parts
C7  HAM A Coildriver  DCC: D1100687_v2 (1.2k ohm)  Rack: SUS-C8  Slot: U23
C8  4-AOSEM Array  DCC: D0901065  Parameter: OM1 HAM6 M1
C9  Cable  value D25-D9 Quadrapus  DCC: D1000228
C10  Cable  value D25-D9 Quadrapus  DCC: D1000228
C16  8 Channel Sat. Amp.  DCC: D1002818  Rack: SUS-R4  Slot: U37
C17  D25 Vacuum Feedthrough  DCC: D1101775 F  Feedthrough: D6-F10  Chamber: HAM6
C82  6-BOSEM Array  Parameter 1: OMC HAM5 TOP  DCC: D060218
C83  Cable  value D25-D9 Quadrapus  DCC: D1000234
C84  Slot: CB-2  DCC: D1001347-4  (hidden comment: Cable Bracket)
C85  Satellite Amplifier  Slot: U17  Rack: SUS-R4  DCC: D0900900
C86  D25 Vacuum Feedthrough  DCC: D1101775 F  Feedthrough: D3-1C1  Chamber: HAM5
C87  OMC Top Coil Driver  Slot: U37  Rack: SUS-C7  DCC: D1100304
C88  Cable  value D25-D9 Quadrapus  DCC: D1000234
C89  Satellite Amplifier  Slot: U17  Rack: SUS-R4  DCC: D0900900
C90  Slot: CB-2  DCC: D1001347-4  (hidden comment: Cable Bracket)
C91  D25 Vacuum Feedthrough  DCC: D1101775 F  Feedthrough: D3-1C2  Chamber: HAM5
C92  OMC Top Coil Driver  Slot: U36  Rack: SUS-C7  DCC: D1100304
C93  HAM A Coildriver  DCC: D1100687_v2 (1.2k ohm)  Rack: SUS-C8  Slot: U22
C94  4-AOSEM Array  DCC: D0901065  Parameter: OM2 HAM6 M1
C95  4-AOSEM Array  DCC: D0901065  Parameter: OM3 HAM6 M1
C96  Cable  value D25-D9 Quadrapus  DCC: D1000228
C97  D25 Vacuum Feedthrough  DCC: D1101775 F  Feedthrough: D6-F9  Chamber: HAM6
C98  HAM A Coildriver  DCC: D1100687_v2 (1.2k ohm)  Rack: SUS-C8  Slot: U12
C99  D25 Vacuum Feedthrough  DCC: D1101775 F  Feedthrough: D6-F12  Chamber: HAM6
C102  8 Channel Sat. Amp.  DCC: D1002818  Rack: SUS-R4  Slot: U34
C112  T-SAMS Heater Driver  DCC: D2000211  Rack: ISC-R5
C113  Slot: CB-7  DCC: D1001347-4  (hidden comment: Cable Bracket)
C114  HTDS T-SAMS  DCC: D2000383  Location: OPTIC CHAMBER STAGE
C115  D25 Vacuum Feedthrough  DCC: D1101775 F  Feedthrough: D6-F11  Chamber: HAM6
C116  HPDS Ethercat  Slot: U41  Rack: PSL-C1  DCC: D1101114

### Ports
OFI_M1_HAMA_Drive (see 3[5A]), OFI_M1_LFRTSDxx_OSEM_PDs (see 5[1B]), OFI_M1_ToSatAmp (see 3[4A]), OM1_M1_CoilDrive (see 5[3C]), OM1_M1_OSEM_PDs (see 5[1B]), OM1_M1_VMONS (see 6[2D]), OM2_M1_CoilDrive (see 5[3C]), OM2_M1_OSEM_PDs (see 5[1B]), OM2_M1_VMONS (see 6[2D]), OM3_M1_CoilDrive (see 5[3C]), OM3_M1_OSEM_PDs (see 5[1B]), OM3_M1_VMONS (see 6[2D]), OMC_TOP_RTSDxxxx_BIO_IN (see 5[5C]), OMC_TOP_RTSDxxxx_BIO_OUT (see 5[5C]), OMC_TOP_RTSDxxxx_CoilDrive (see 5[3B]), OMC_TOP_RTSDxxxx_NOISEMON (see 6[2B]), OMC_TOP_RTSDxxxx_OSEM_PDs (see 5[1B]), OMC_TOP_RTSDxxxx_SFVMONS (see 6[2B]), OMC_TOP_T1T2T3LF_BIO_IN (see 5[5C]), OMC_TOP_T1T2T3LF_BIO_OUT (see 5[5C]), OMC_TOP_T1T2T3LF_CoilDrive (see 5[3B]), OMC_TOP_T1T2T3LF_NOISEMON (see 6[2B]), OMC_TOP_T1T2T3LF_OSEM_PDs (see 5[1B]), OMC_TOP_T1T2T3LF_SFVMONS (see 6[2B])

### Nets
ISC_127: C16.D9F(Ch_1-4_PD_Out) ; port OM1_M1_OSEM_PDs
ISC_128: C16.D9F(Ch_5-8_PD_Out) ; port OM2_M1_OSEM_PDs
ISC_129: C102.D9F(Ch_1-4_PD_Out) ; port OM3_M1_OSEM_PDs
ISC_186: C7.D9F(PD_Inputs) ; port OM1_M1_VMONS
ISC_187: C93.D9F(PD_Inputs) ; port OM2_M1_VMONS
ISC_188: C98.D9F(PD_Inputs) ; port OM3_M1_VMONS
ISC_189: C7.D9M(Coil_Inputs) ; port OM1_M1_CoilDrive
ISC_190: C93.D9M(Coil_Inputs) ; port OM2_M1_CoilDrive
ISC_191: C98.D9M(Coil_Inputs) ; port OM3_M1_CoilDrive
ISC_196: C7.D15F(Coil_Driver_Out) C16.D9M(Ch_1-4_Coil_Drive_In)
ISC_197: C16.D9M(Ch_5-8_Coil_Drive_In) C93.D15F(Coil_Driver_Out)
ISC_198: C98.D15F(Coil_Driver_Out) C102.D9M(Ch_1-4_Coil_Drive_In)
ISC_236: C16.D25F(Chan_1-4) C17.D25M(Air_Side)
ISC_237: C16.D25F(Chan_5-8) C97.D25M(Air_Side)
ISC_238: C99.D25M(Air_Side) C102.D25F(Chan_1-4)
SUS_HAM5_052: C92.D37M(Binary_IO_2) ; port OMC_TOP_RTSDxxxx_BIO_OUT
SUS_HAM6_010: C85.D25F(To_Vacuum_Chamber) C86.D25M(Air_Side)
SUS_HAM6_011: C89.D25F(To_Vacuum_Chamber) C91.D25M(Air_Side)
SUS_HAM6_013: C85.D25M(Monitors_to_ADC) C87.D25F(PD_in_From_Sat)
SUS_HAM6_014: C85.D15M(Coil_Drive_Interface) C87.D15F(Coil_Out_to_Sat)
SUS_HAM6_015: C89.D25M(Monitors_to_ADC) C92.D25F(PD_in_From_Sat)
SUS_HAM6_016: C89.D15M(Coil_Drive_Interface) C92.D15F(Coil_Out_to_Sat)
SUS_HAM6_049: C87.D37F(Binary_IO_1) ; port OMC_TOP_T1T2T3LF_BIO_IN
SUS_HAM6_050: C87.D37M(Binary_IO_2) ; port OMC_TOP_T1T2T3LF_BIO_OUT
SUS_HAM6_051: C92.D37F(Binary_IO_1) ; port OMC_TOP_RTSDxxxx_BIO_IN
SUS_HAM6_074: C87.D9F(PD_Out_to_AA) ; port OMC_TOP_T1T2T3LF_OSEM_PDs
SUS_HAM6_075: C92.D9F(PD_Out_to_AA) ; port OMC_TOP_RTSDxxxx_OSEM_PDs
SUS_HAM6_094: C87.D9M(Test_In) ; port OMC_TOP_T1T2T3LF_CoilDrive
SUS_HAM6_098: C92.D9M(Test_In) ; port OMC_TOP_RTSDxxxx_CoilDrive
SUS_HAM6_126: C87.D9F(Noise_Monitor) ; port OMC_TOP_T1T2T3LF_NOISEMON
SUS_HAM6_128: C87.D25M(VI_&_RMS_Monitor) ; port OMC_TOP_T1T2T3LF_SFVMONS
SUS_HAM6_131: C92.D9F(Noise_Monitor) ; port OMC_TOP_RTSDxxxx_NOISEMON
SUS_HAM6_133: C92.D25M(VI_&_RMS_Monitor) ; port OMC_TOP_RTSDxxxx_SFVMONS
SUS_HAM6_163A: C82.D9F(TOP1) C83.MicroD9(Q1)
SUS_HAM6_163B: C82.D9F(TOP2) C83.MicroD9(Q2)
SUS_HAM6_163C: C82.D9F(TOP3) C83.MicroD9(Q3)
SUS_HAM6_163D: C82.D9F(LEFT) C83.MicroD9(Q4)
SUS_HAM6_163E: C83.D25M(Flange) C84.D25M
SUS_HAM6_164: C84.D25F C86.D25M(Vac._Side)
SUS_HAM6_165A: C82.D9F(RIGHT) C88.MicroD9(Q1)
SUS_HAM6_165B: C82.D9F(SIDE) C88.MicroD9(Q2)
SUS_HAM6_165E: C88.D25M(Flange) C90.D25M
SUS_HAM6_166: C90.D25F C91.D25M(Vac._Side)
SUS_OM2_001: C112.D25F(To_Vacuum_Feedthrough_HTDS_1) C115.D25M(Air_Side)
SUS_SQ_30: C102.D25F(Chan_5-8) ; port OFI_M1_ToSatAmp
SUS_SQ_031: C102.D9M(Ch_5-8_Coil_Drive_In) ; port OFI_M1_HAMA_Drive
SUS_SQ_032: C102.D9F(Ch_5-8_PD_Out) ; port OFI_M1_LFRTSDxx_OSEM_PDs
VAC_OM1_001A: C8.D9F(UL) C9.MicroD9(Q1)
VAC_OM1_001B: C8.D9F(LL) C9.MicroD9(Q2)
VAC_OM1_001C: C8.D9F(UR) C9.MicroD9(Q3)
VAC_OM1_001D: C8.D9F(LR) C9.MicroD9(Q4)
VAC_OM1_002: C9.D25M(Flange) C17.D25M(Vac._Side)
VAC_OM2_001A: C10.MicroD9(Q1) C94.D9F(UL)
VAC_OM2_001B: C10.MicroD9(Q2) C94.D9F(LL)
VAC_OM2_001C: C10.MicroD9(Q3) C94.D9F(UR)
VAC_OM2_001D: C10.MicroD9(Q4) C94.D9F(LR)
VAC_OM2_002: C10.D25M(Flange) C97.D25M(Vac._Side)
VAC_OM2_003: C113.D25M C114.MM-7P-M(T-SAMS)
VAC_OM2_004: C113.D25F C115.D25M(Vac._Side)
VAC_OM3_001A: C95.D9F(UL) C96.MicroD9(Q1)
VAC_OM3_001B: C95.D9F(LL) C96.MicroD9(Q2)
VAC_OM3_001C: C95.D9F(UR) C96.MicroD9(Q3)
VAC_OM3_001D: C95.D9F(LR) C96.MicroD9(Q4)
VAC_OM3_002: C96.D25M(Flange) C99.D25M(Vac._Side)
NetC112_D25M: C112.D25M(To_Beckhoff_Interface_Output_1) C116.DB25F(Slot_1)

Not connected (* = marked no-connect by the designer): C7 Conec-3(DC+/-18)* D25F(To/From_Sat_Amp)*; C16 Conec-3(DC_IN_+/-18)*; C85 Conec 3(DC_±18v)* D37F(Local_Diagnostics)*; C87 Conec 3(DC_±18v)*; C89 Conec 3(DC_±18v)* D37F(Local_Diagnostics)*; C92 Conec 3(DC_±18v)*; C93 Conec-3(DC+/-18)* D25F(To/From_Sat_Amp)*; C98 Conec-3(DC+/-18)* D25F(To/From_Sat_Amp)*; C102 Conec-3(DC_IN_+/-18)*; C112 Conec-3(DC_IN_+/-18)*; C116 Conec-3(+24VDC)* DB15M(Slot_3)* DB25M(Slot_8)* LC-Fiber(IN)* PICOMOTOR(Slot_4)* RJ-45(Port_1A)* Rot. Stage(Slot_9)*

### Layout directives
Length: 5ft; DCC: Dxxxxxxx: ISC_186, ISC_187, ISC_188, ISC_189, ISC_190, ISC_191, SUS_HAM5_052, SUS_HAM6_049, SUS_HAM6_050, SUS_HAM6_051, SUS_HAM6_074, SUS_HAM6_075, SUS_HAM6_094, SUS_HAM6_098, SUS_HAM6_126, SUS_HAM6_128, SUS_HAM6_131, SUS_HAM6_133
Length: ?ft; DCC: Dxxxxxxx: SUS_HAM6_013, SUS_HAM6_014, SUS_HAM6_015, SUS_HAM6_016
Length: 6.5ft; DCC: Connector J1(E): SUS_HAM6_163E, SUS_HAM6_165E
Length: 13ft; DCC: D1000225: SUS_HAM6_164, SUS_HAM6_166, VAC_OM3_002
Length: ?ft; DCC: D2100464: ISC_236, ISC_237, ISC_238, SUS_HAM6_010, SUS_HAM6_011, SUS_OM2_001
Length: 6.5ft; DCC: Connector J2(A): SUS_HAM6_163A, SUS_HAM6_165A
Length: 6.5ft; DCC: Connector J3(B): SUS_HAM6_163B, SUS_HAM6_165B
Length: 6.5ft; DCC: Connector J4(C): SUS_HAM6_163C
Length: 6.5ft; DCC: Connector J5(D): SUS_HAM6_163D
Length: 9ft; DCC: D1000225: VAC_OM1_002
Length: 5ft; DCC: Connector J5(D): VAC_OM1_001D, VAC_OM2_001D, VAC_OM3_001D
Length: 8ft; DCC: Connector J2(A): VAC_OM1_001A, VAC_OM2_001A, VAC_OM3_001A
Length: 5ft; DCC: Connector  J3(B): VAC_OM1_001B, VAC_OM2_001B, VAC_OM3_001B
Length: 8ft; DCC: Connector J4(C): VAC_OM1_001C, VAC_OM2_001C, VAC_OM3_001C
Length: ?ft; DCC: -: ISC_127, ISC_128, ISC_129, ISC_196, ISC_197, ISC_198, SUS_SQ_031, SUS_SQ_032
Length: 15ft; DCC: D1000225: VAC_OM2_002
Length: 6ft; DCC: D2000403: VAC_OM2_003
Length: 15ft; DCC: D2000476: VAC_OM2_004

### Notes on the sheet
- (near C82) OMC TOP
- (near C86) See D1101917 for Flange Assignments
- OM1-M1
- OM2-M1
- See D1101114
- Reserved
- OM2-M2
- Reserved.  See D2000202
- Spare
- OM3-M1

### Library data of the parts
C7 C93 C98 = HAM A Coildriver: Serial: Sxxxxxxx; System: ISC
C8 C94 C95 = 4-BOSEM Array: as C70 on sheet HAM5_SR3
C9 C10 C83 C88 C96 = Flange: as C3 on sheet HAM5_SR3
C16 C102 = 8 Channel Sat. Amp.: Serial: Sxxxxxxx; System: ISC
C17 C86 C91 C97 C99 C115 = VacFeedD25: as C6 on sheet HAM5_SR3
C82 = 6-BOSEM Array HAM: as C64 on sheet HAM5_SR3
C84 C113 = Cable Bracket 2 1-4: as C73 on sheet HAM5_SR3
C85 C89 = Satellite Amplifier: System: SUS; Serial: Sxxxxxxx
C87 C92 = OMC Top CD: System: SUS; Serial: Sxxxxxxx
C90 = Cable Bracket 3 1-4: as C66 on sheet HAM5_SR3
C112 = T-SAMS Heater Driver: Serial: Sxxxxxxx
C114 = HTDS T-SAMS: Heater and two thermistors; Rack: SUS-R?; Serial: Sxxxxxxx; Slot: U?; System: SUS
C116 = HPDS Ethercat: PSL - C1; System: MISC; Serial: Sxxxxxxx

## Sheet SUSH56_ADC_DAC.SchDoc: SUS HAM56 Controls IO Chains
size C; Engineer: L. Sanchez; Organization: LIGO Laboratory; Address1: California Institute of Technology; Address2: Massachusetts Institute of Technology; DocumentNumber: D1002740; Revision: v9; SheetNumber: 5; SheetTotal: 8
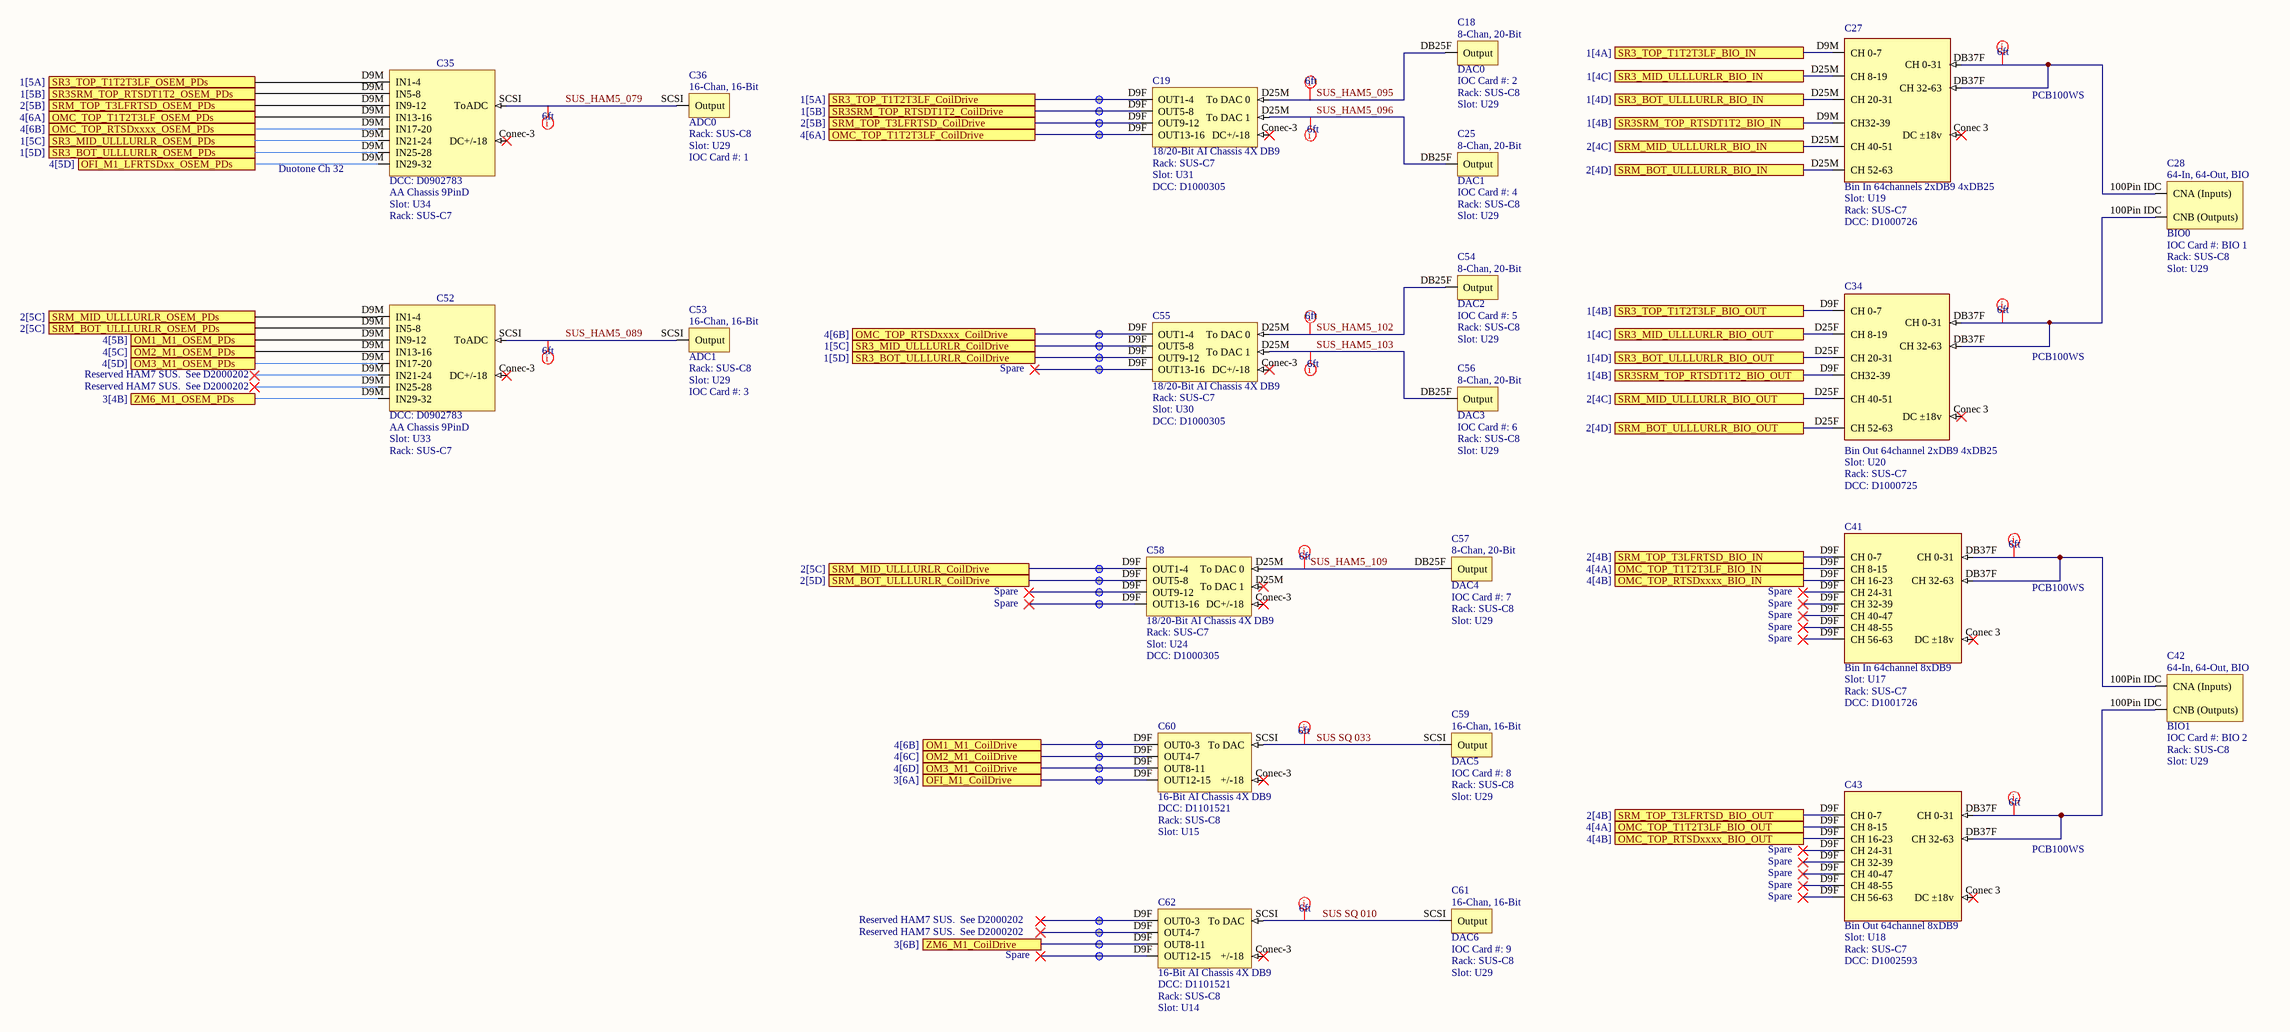
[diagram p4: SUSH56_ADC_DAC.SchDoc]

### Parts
C18  DAC0  IOC Card #: 2  Rack: SUS-C8  Slot: U29
C19  18/20-Bit AI Chassis 4X DB9  Rack: SUS-C7  Slot: U31  DCC: D1000305
C25  DAC1  IOC Card #: 4  Rack: SUS-C8  Slot: U29
C27  Bin In 64channels 2xDB9 4xDB25  Slot: U19  Rack: SUS-C7  DCC: D1000726
C28  BIO0  IOC Card #: BIO 1  Rack: SUS-C8  Slot: U29
C34  Bin Out 64channel 2xDB9 4xDB25  Slot: U20  Rack: SUS-C7  DCC: D1000725
C35  AA Chassis 9PinD  DCC: D0902783  Rack: SUS-C7  Slot: U34
C36  ADC0  Rack: SUS-C8  Slot: U29  IOC Card #: 1
C41  Bin In 64channel 8xDB9  Slot: U17  Rack: SUS-C7  DCC: D1001726
C42  BIO1  IOC Card #: BIO 2  Rack: SUS-C8  Slot: U29
C43  Bin Out 64channel 8xDB9  Slot: U18  Rack: SUS-C7  DCC: D1002593
C52  AA Chassis 9PinD  DCC: D0902783  Rack: SUS-C7  Slot: U33
C53  ADC1  Rack: SUS-C8  Slot: U29  IOC Card #: 3
C54  DAC2  IOC Card #: 5  Rack: SUS-C8  Slot: U29
C55  18/20-Bit AI Chassis 4X DB9  Rack: SUS-C7  Slot: U30  DCC: D1000305
C56  DAC3  IOC Card #: 6  Rack: SUS-C8  Slot: U29
C57  DAC4  IOC Card #: 7  Rack: SUS-C8  Slot: U29
C58  18/20-Bit AI Chassis 4X DB9  Rack: SUS-C7  Slot: U24  DCC: D1000305
C59  DAC5  IOC Card #: 8  Rack: SUS-C8  Slot: U29
C60  16-Bit AI Chassis 4X DB9  DCC: D1101521  Rack: SUS-C8  Slot: U15
C61  DAC6  IOC Card #: 9  Rack: SUS-C8  Slot: U29
C62  16-Bit AI Chassis 4X DB9  DCC: D1101521  Rack: SUS-C8  Slot: U14

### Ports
OFI_M1_CoilDrive (see 3[6A]), OFI_M1_LFRTSDxx_OSEM_PDs (see 4[5D]), OM1_M1_CoilDrive (see 4[6B]), OM1_M1_OSEM_PDs (see 4[5B]), OM2_M1_CoilDrive (see 4[6C]), OM2_M1_OSEM_PDs (see 4[5C]), OM3_M1_CoilDrive (see 4[6D]), OM3_M1_OSEM_PDs (see 4[5D]), OMC_TOP_RTSDxxxx_BIO_IN (see 4[4B]), OMC_TOP_RTSDxxxx_BIO_OUT (see 4[4B]), OMC_TOP_RTSDxxxx_CoilDrive (see 4[6B]), OMC_TOP_RTSDxxxx_OSEM_PDs (see 4[6B]), OMC_TOP_T1T2T3LF_BIO_IN (see 4[4A]), OMC_TOP_T1T2T3LF_BIO_OUT (see 4[4A]), OMC_TOP_T1T2T3LF_CoilDrive (see 4[6A]), OMC_TOP_T1T2T3LF_OSEM_PDs (see 4[6A]), SR3_BOT_ULLLURLR_BIO_IN (see 1[4D]), SR3_BOT_ULLLURLR_BIO_OUT (see 1[4D]), SR3_BOT_ULLLURLR_CoilDrive (see 1[5D]), SR3_BOT_ULLLURLR_OSEM_PDs (see 1[5D]), SR3_MID_ULLLURLR_BIO_IN (see 1[4C]), SR3_MID_ULLLURLR_BIO_OUT (see 1[4C]), SR3_MID_ULLLURLR_CoilDrive (see 1[5C]), SR3_MID_ULLLURLR_OSEM_PDs (see 1[5C]), SR3_TOP_T1T2T3LF_BIO_IN (see 1[4A]), SR3_TOP_T1T2T3LF_BIO_OUT (see 1[4B]), SR3_TOP_T1T2T3LF_CoilDrive (see 1[5A]), SR3_TOP_T1T2T3LF_OSEM_PDs (see 1[5A]), SR3SRM_TOP_RTSDT1T2_BIO_IN (see 1[4B]), SR3SRM_TOP_RTSDT1T2_BIO_OUT (see 1[4B]), SR3SRM_TOP_RTSDT1T2_CoilDrive (see 1[5B]), SR3SRM_TOP_RTSDT1T2_OSEM_PDs (see 1[5B]), SRM_BOT_ULLLURLR_BIO_IN (see 2[4D]), SRM_BOT_ULLLURLR_BIO_OUT (see 2[4D]), SRM_BOT_ULLLURLR_CoilDrive (see 2[5D]), SRM_BOT_ULLLURLR_OSEM_PDs (see 2[5C]), SRM_MID_ULLLURLR_BIO_IN (see 2[4C]), SRM_MID_ULLLURLR_BIO_OUT (see 2[4C]), SRM_MID_ULLLURLR_CoilDrive (see 2[5C]), SRM_MID_ULLLURLR_OSEM_PDs (see 2[5C]), SRM_TOP_T3LFRTSD_BIO_IN (see 2[4B]), SRM_TOP_T3LFRTSD_BIO_OUT (see 2[4B]), SRM_TOP_T3LFRTSD_CoilDrive (see 2[5B]), SRM_TOP_T3LFRTSD_OSEM_PDs (see 2[5B]), ZM6_M1_CoilDrive (see 3[6B]), ZM6_M1_OSEM_PDs (see 3[4B])

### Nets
ISC_127: C52.D9M(IN9-12) ; port OM1_M1_OSEM_PDs
ISC_128: C52.D9M(IN13-16) ; port OM2_M1_OSEM_PDs
ISC_129: C52.D9M(IN17-20) ; port OM3_M1_OSEM_PDs
ISC_189: C60.D9F(OUT0-3) ; port OM1_M1_CoilDrive
ISC_190: C60.D9F(OUT4-7) ; port OM2_M1_CoilDrive
ISC_191: C60.D9F(OUT8-11) ; port OM3_M1_CoilDrive
SUS SQ 010: C61.SCSI(Output) C62.SCSI(To_DAC)
SUS SQ 033: C59.SCSI(Output) C60.SCSI(To_DAC)
SUS_HAM5_043: C27.D9M(CH_0-7) ; port SR3_TOP_T1T2T3LF_BIO_IN
SUS_HAM5_044: C34.D9F(CH_0-7) ; port SR3_TOP_T1T2T3LF_BIO_OUT
SUS_HAM5_045: C27.D9M(CH32-39) ; port SR3SRM_TOP_RTSDT1T2_BIO_IN
SUS_HAM5_046: C34.D9F(CH32-39) ; port SR3SRM_TOP_RTSDT1T2_BIO_OUT
SUS_HAM5_047: C41.D9F(CH_0-7) ; port SRM_TOP_T3LFRTSD_BIO_IN
SUS_HAM5_048: C43.D9F(CH_0-7) ; port SRM_TOP_T3LFRTSD_BIO_OUT
SUS_HAM5_052: C43.D9F(CH_16-23) ; port OMC_TOP_RTSDxxxx_BIO_OUT
SUS_HAM5_055: C27.D25M(CH_8-19) ; port SR3_MID_ULLLURLR_BIO_IN
SUS_HAM5_056: C34.D25F(CH_8-19) ; port SR3_MID_ULLLURLR_BIO_OUT
SUS_HAM5_057: C27.D25M(CH_20-31) ; port SR3_BOT_ULLLURLR_BIO_IN
SUS_HAM5_058: C34.D25F(CH_20-31) ; port SR3_BOT_ULLLURLR_BIO_OUT
SUS_HAM5_059: C27.D25M(CH_40-51) ; port SRM_MID_ULLLURLR_BIO_IN
SUS_HAM5_060: C34.D25F(CH_40-51) ; port SRM_MID_ULLLURLR_BIO_OUT
SUS_HAM5_061: C27.D25M(CH_52-63) ; port SRM_BOT_ULLLURLR_BIO_IN
SUS_HAM5_062: C34.D25F(CH_52-63) ; port SRM_BOT_ULLLURLR_BIO_OUT
SUS_HAM5_071: C35.D9M(IN1-4) ; port SR3_TOP_T1T2T3LF_OSEM_PDs
SUS_HAM5_072: C35.D9M(IN5-8) ; port SR3SRM_TOP_RTSDT1T2_OSEM_PDs
SUS_HAM5_073: C35.D9M(IN9-12) ; port SRM_TOP_T3LFRTSD_OSEM_PDs
SUS_HAM5_077: C35.D9M(IN21-24) ; port SR3_MID_ULLLURLR_OSEM_PDs
SUS_HAM5_079: C35.SCSI(ToADC) C36.SCSI(Output)
SUS_HAM5_081: C35.D9M(IN25-28) ; port SR3_BOT_ULLLURLR_OSEM_PDs
SUS_HAM5_082: C52.D9M(IN1-4) ; port SRM_MID_ULLLURLR_OSEM_PDs
SUS_HAM5_083: C52.D9M(IN5-8) ; port SRM_BOT_ULLLURLR_OSEM_PDs
SUS_HAM5_089: C52.SCSI(ToADC) C53.SCSI(Output)
SUS_HAM5_091: C19.D9F(OUT1-4) ; port SR3_TOP_T1T2T3LF_CoilDrive
SUS_HAM5_092: C19.D9F(OUT5-8) ; port SR3SRM_TOP_RTSDT1T2_CoilDrive
SUS_HAM5_093: C19.D9F(OUT9-12) ; port SRM_TOP_T3LFRTSD_CoilDrive
SUS_HAM5_095: C18.DB25F(Output) C19.D25M(To_DAC_0)
SUS_HAM5_096: C19.D25M(To_DAC_1) C25.DB25F(Output)
SUS_HAM5_100: C55.D9F(OUT5-8) ; port SR3_MID_ULLLURLR_CoilDrive
SUS_HAM5_101: C55.D9F(OUT9-12) ; port SR3_BOT_ULLLURLR_CoilDrive
SUS_HAM5_102: C54.DB25F(Output) C55.D25M(To_DAC_0)
SUS_HAM5_103: C55.D25M(To_DAC_1) C56.DB25F(Output)
SUS_HAM5_105: C58.D9F(OUT1-4) ; port SRM_MID_ULLLURLR_CoilDrive
SUS_HAM5_106: C58.D9F(OUT5-8) ; port SRM_BOT_ULLLURLR_CoilDrive
SUS_HAM5_109: C57.DB25F(Output) C58.D25M(To_DAC_0)
SUS_HAM6_049: C41.D9F(CH_8-15) ; port OMC_TOP_T1T2T3LF_BIO_IN
SUS_HAM6_050: C43.D9F(CH_8-15) ; port OMC_TOP_T1T2T3LF_BIO_OUT
SUS_HAM6_051: C41.D9F(CH_16-23) ; port OMC_TOP_RTSDxxxx_BIO_IN
SUS_HAM6_074: C35.D9M(IN13-16) ; port OMC_TOP_T1T2T3LF_OSEM_PDs
SUS_HAM6_075: C35.D9M(IN17-20) ; port OMC_TOP_RTSDxxxx_OSEM_PDs
SUS_HAM6_094: C19.D9F(OUT13-16) ; port OMC_TOP_T1T2T3LF_CoilDrive
SUS_HAM6_098: C55.D9F(OUT1-4) ; port OMC_TOP_RTSDxxxx_CoilDrive
SUS_SQ_032: C35.D9M(IN29-32) ; port OFI_M1_LFRTSDxx_OSEM_PDs
SUS_SQ_33: C60.D9F(OUT12-15) ; port OFI_M1_CoilDrive
SUS_ZM6_25: C52.D9M(IN29-32) ; port ZM6_M1_OSEM_PDs
SUS_ZM6_28: C62.D9F(OUT0-3) ; port ZM6_M1_CoilDrive
NetC27_DB37F: C27.DB37F(CH_0-31) C28.100Pin_IDC(CNA_(Inputs))
NetC28_100Pin IDC: C28.100Pin_IDC(CNB_(Outputs)) C34.DB37F(CH_0-31)
NetC41_DB37F: C41.DB37F(CH_0-31) C42.100Pin_IDC(CNA_(Inputs))
NetC42_100Pin IDC: C42.100Pin_IDC(CNB_(Outputs)) C43.DB37F(CH_0-31)

Not connected (* = marked no-connect by the designer): C19 Conec-3(DC+/-18)*; C27 Conec 3(DC_±18v)*; C34 Conec 3(DC_±18v)*; C35 Conec-3(DC+/-18)*; C41 Conec 3(DC_±18v)*; C43 Conec 3(DC_±18v)*; C52 Conec-3(DC+/-18)*; C55 Conec-3(DC+/-18)*; C58 Conec-3(DC+/-18)*; C60 Conec-3(+/-18)*; C62 Conec-3(+/-18)*

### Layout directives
Length: 6ft; DCC: Dxxxxxxx: NetC27_DB37F, NetC28_100Pin IDC, NetC41_DB37F, NetC42_100Pin IDC, SUS SQ 010, SUS SQ 033, SUS_HAM5_079, SUS_HAM5_089, SUS_HAM5_095, SUS_HAM5_096, SUS_HAM5_102, SUS_HAM5_103, SUS_HAM5_109

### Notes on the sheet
- PCB100WS
- (near C35) Duotone Ch 32
- Reserved HAM7 SUS.  See D2000202
- Spare

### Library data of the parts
C18 C25 C54 C56 C57 = DAC-20: 8 Chan, 20 Bit DAC
C19 C55 C58 = AI_9Pin_18_20_Bit: System: SUS; Serial: Sxxxxxxx
C27 = Bin_In_64ch_2xDB9_4xDB25: Serial: Sxxxxxxx; System: SUS
C28 C42 = Binary IO: 128 Chan, Contec DIO-6464L-PE
C34 = Bin_Out_64ch_2xDB9_4xDB25: Serial: Sxxxxxxx; System: SUS
C35 C52 = AA_9pinAll: ISC AA Chassis 9PinD; Serial: Sxxxxxxx
C36 C53 = ADC-16: 16 Chan, 16 Bit ADC
C41 = Bin In 64cha_8xDB9: Serial: Sxxxxxxx; System: SUS
C43 = Bin Out 64cha_8xDB9: Serial: Sxxxxxxx; System: SUS
C59 C61 = DAC-16: 16 Chan, 16 Bit DAC
C60 C62 = AI_9pin_16_bit: AI Chassis 4X DB9 16-bit; Serial: Sxxxxxxx; System: ISC

## Sheet SUSAUXH56_ADC_DAC.SchDoc: SUS AUX HAM56 Coil Mon. IO Chains
size B; Engineer: L. Sanchez; Organization: LIGO Laboratory; Address1: California Institute of Technology; Address2: Massachusetts Institute of Technology; DocumentNumber: D1002740; Revision: v9; SheetNumber: 6; SheetTotal: 8
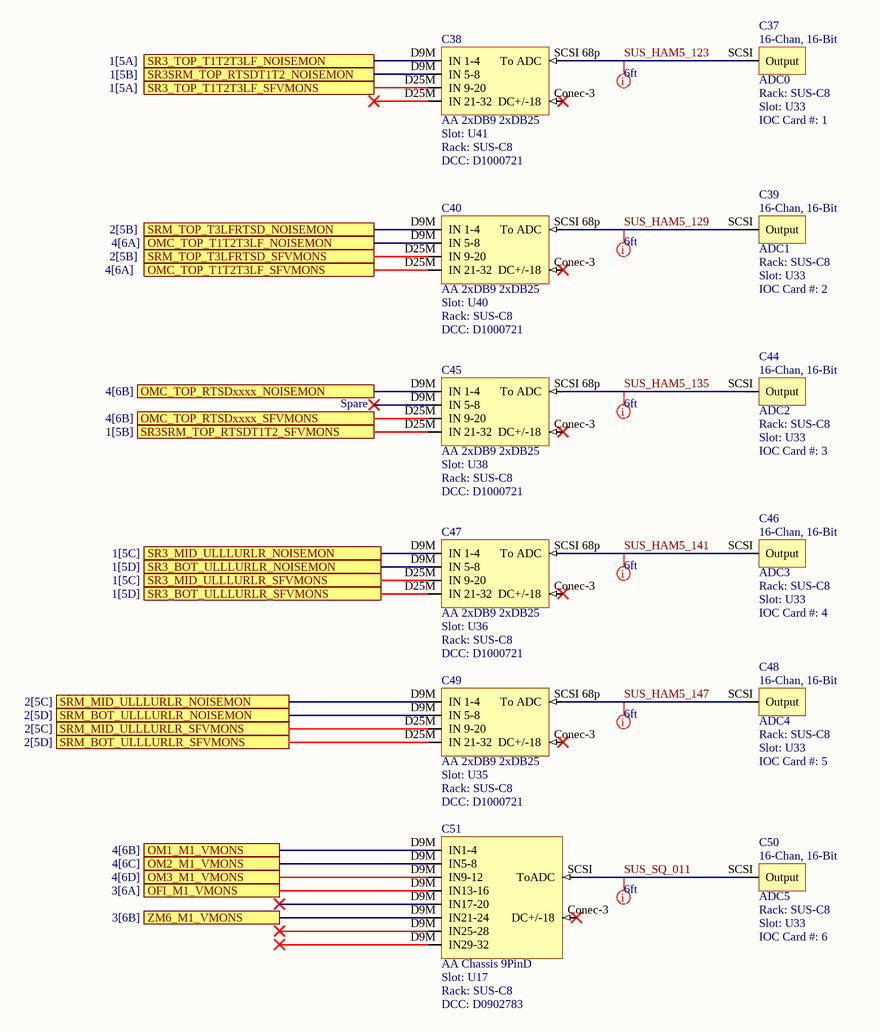
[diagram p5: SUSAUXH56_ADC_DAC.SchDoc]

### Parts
C37  ADC0  Rack: SUS-C8  Slot: U33  IOC Card #: 1
C38  AA 2xDB9 2xDB25  Slot: U41  Rack: SUS-C8  DCC: D1000721
C39  ADC1  Rack: SUS-C8  Slot: U33  IOC Card #: 2
C40  AA 2xDB9 2xDB25  Slot: U40  Rack: SUS-C8  DCC: D1000721
C44  ADC2  Rack: SUS-C8  Slot: U33  IOC Card #: 3
C45  AA 2xDB9 2xDB25  Slot: U38  Rack: SUS-C8  DCC: D1000721
C46  ADC3  Rack: SUS-C8  Slot: U33  IOC Card #: 4
C47  AA 2xDB9 2xDB25  Slot: U36  Rack: SUS-C8  DCC: D1000721
C48  ADC4  Rack: SUS-C8  Slot: U33  IOC Card #: 5
C49  AA 2xDB9 2xDB25  Slot: U35  Rack: SUS-C8  DCC: D1000721
C50  ADC5  Rack: SUS-C8  Slot: U33  IOC Card #: 6
C51  AA Chassis 9PinD  Slot: U17  Rack: SUS-C8  DCC: D0902783

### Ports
OFI_M1_VMONS (see 3[6A]), OM1_M1_VMONS (see 4[6B]), OM2_M1_VMONS (see 4[6C]), OM3_M1_VMONS (see 4[6D]), OMC_TOP_RTSDxxxx_NOISEMON (see 4[6B]), OMC_TOP_RTSDxxxx_SFVMONS (see 4[6B]), OMC_TOP_T1T2T3LF_NOISEMON (see 4[6A]), OMC_TOP_T1T2T3LF_SFVMONS (see 4[6A]), SR3_BOT_ULLLURLR_NOISEMON (see 1[5D]), SR3_BOT_ULLLURLR_SFVMONS (see 1[5D]), SR3_MID_ULLLURLR_NOISEMON (see 1[5C]), SR3_MID_ULLLURLR_SFVMONS (see 1[5C]), SR3_TOP_T1T2T3LF_NOISEMON (see 1[5A]), SR3_TOP_T1T2T3LF_SFVMONS (see 1[5A]), SR3SRM_TOP_RTSDT1T2_NOISEMON (see 1[5B]), SR3SRM_TOP_RTSDT1T2_SFVMONS (see 1[5B]), SRM_BOT_ULLLURLR_NOISEMON (see 2[5D]), SRM_BOT_ULLLURLR_SFVMONS (see 2[5D]), SRM_MID_ULLLURLR_NOISEMON (see 2[5C]), SRM_MID_ULLLURLR_SFVMONS (see 2[5C]), SRM_TOP_T3LFRTSD_NOISEMON (see 2[5B]), SRM_TOP_T3LFRTSD_SFVMONS (see 2[5B]), ZM6_M1_VMONS (see 3[6B])

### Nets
ISC_186: C51.D9M(IN1-4) ; port OM1_M1_VMONS
ISC_187: C51.D9M(IN5-8) ; port OM2_M1_VMONS
ISC_188: C51.D9M(IN9-12) ; port OM3_M1_VMONS
SUS_HAM5_119: C38.D9M(IN_1-4) ; port SR3_TOP_T1T2T3LF_NOISEMON
SUS_HAM5_120: C38.D9M(IN_5-8) ; port SR3SRM_TOP_RTSDT1T2_NOISEMON
SUS_HAM5_121: C38.D25M(IN_9-20) ; port SR3_TOP_T1T2T3LF_SFVMONS
SUS_HAM5_122: C45.D25M(IN_21-32) ; port SR3SRM_TOP_RTSDT1T2_SFVMONS
SUS_HAM5_123: C37.SCSI(Output) C38.SCSI_68p(To_ADC)
SUS_HAM5_125: C40.D9M(IN_1-4) ; port SRM_TOP_T3LFRTSD_NOISEMON
SUS_HAM5_127: C40.D25M(IN_9-20) ; port SRM_TOP_T3LFRTSD_SFVMONS
SUS_HAM5_129: C39.SCSI(Output) C40.SCSI_68p(To_ADC)
SUS_HAM5_135: C44.SCSI(Output) C45.SCSI_68p(To_ADC)
SUS_HAM5_137: C47.D9M(IN_1-4) ; port SR3_MID_ULLLURLR_NOISEMON
SUS_HAM5_138: C47.D9M(IN_5-8) ; port SR3_BOT_ULLLURLR_NOISEMON
SUS_HAM5_139: C47.D25M(IN_9-20) ; port SR3_MID_ULLLURLR_SFVMONS
SUS_HAM5_140: C47.D25M(IN_21-32) ; port SR3_BOT_ULLLURLR_SFVMONS
SUS_HAM5_141: C46.SCSI(Output) C47.SCSI_68p(To_ADC)
SUS_HAM5_143: C49.D9M(IN_1-4) ; port SRM_MID_ULLLURLR_NOISEMON
SUS_HAM5_144: C49.D9M(IN_5-8) ; port SRM_BOT_ULLLURLR_NOISEMON
SUS_HAM5_145: C49.D25M(IN_9-20) ; port SRM_MID_ULLLURLR_SFVMONS
SUS_HAM5_146: C49.D25M(IN_21-32) ; port SRM_BOT_ULLLURLR_SFVMONS
SUS_HAM5_147: C48.SCSI(Output) C49.SCSI_68p(To_ADC)
SUS_HAM6_126: C40.D9M(IN_5-8) ; port OMC_TOP_T1T2T3LF_NOISEMON
SUS_HAM6_128: C40.D25M(IN_21-32) ; port OMC_TOP_T1T2T3LF_SFVMONS
SUS_HAM6_131: C45.D9M(IN_1-4) ; port OMC_TOP_RTSDxxxx_NOISEMON
SUS_HAM6_133: C45.D25M(IN_9-20) ; port OMC_TOP_RTSDxxxx_SFVMONS
SUS_SQ_011: C50.SCSI(Output) C51.SCSI(ToADC)
SUS_SQ_34: C51.D9M(IN13-16) ; port OFI_M1_VMONS
SUS_ZM6_29: C51.D9M(IN21-24) ; port ZM6_M1_VMONS

Not connected (* = marked no-connect by the designer): C38 Conec-3(DC+/-18)*; C40 Conec-3(DC+/-18)*; C45 Conec-3(DC+/-18)*; C47 Conec-3(DC+/-18)*; C49 Conec-3(DC+/-18)*; C51 Conec-3(DC+/-18)*

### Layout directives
Length: 6ft; DCC: Dxxxxxxx: SUS_HAM5_123, SUS_HAM5_129, SUS_HAM5_135, SUS_HAM5_141, SUS_HAM5_147, SUS_SQ_011

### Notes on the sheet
- Spare

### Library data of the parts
C37 C39 C44 C46 C48 C50 = ADC-16: 16 Chan, 16 Bit ADC
C38 C40 C45 C47 C49 = AA 2xDB9M 2xDB25M: System: SUS; Serial: Sxxxxxxx
C51 = AA_9pinAll: ISC AA Chassis 9PinD; Serial: Sxxxxxxx

## Sheet RACK_SUS_R4.SchDoc: FIELD RACK SUS-R4
size C; Engineer: L. Sanchez; Organization: LIGO Laboratory; Address1: California Institute of Technology; Address2: Massachusetts Institute of Technology; DocumentNumber: D1002740; Revision: v9; SheetNumber: 7; SheetTotal: 8
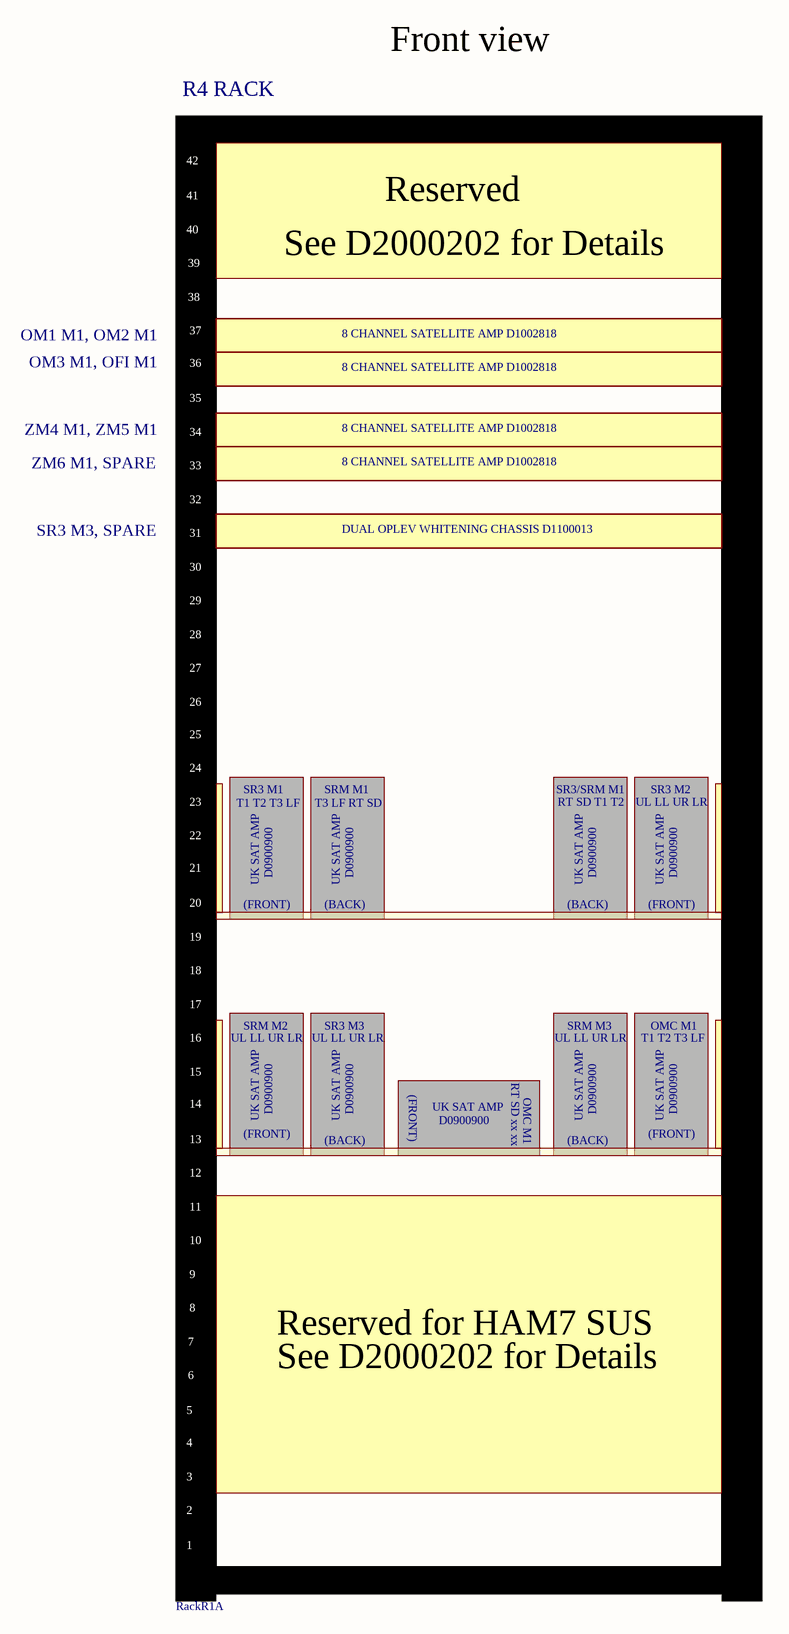
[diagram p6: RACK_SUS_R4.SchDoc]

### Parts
RackR1  1U  Rack 42 pos  (value not drawn)  (part A of 2)

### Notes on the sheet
- Front view
- R4 RACK
- Reserved
- See D2000202 for Details
- OM1 M1, OM2 M1
- 8 CHANNEL SATELLITE AMP D1002818
- OM3 M1, OFI M1
- ZM4 M1, ZM5 M1
- ZM6 M1, SPARE
- SR3 M3, SPARE
- DUAL OPLEV WHITENING CHASSIS D1100013
- T1 T2 T3 LF
- SR3 M1
- T3 LF RT SD
- SRM M1
- SR3/SRM M1
- RT SD T1 T2
- UL LL UR LR
- SR3 M2
- UK SAT AMP
- D0900900
- (FRONT)
- (BACK)
- SRM M2
- SR3 M3
- RT SD xx xx
- SRM M3
- OMC M1
- Reserved for HAM7 SUS

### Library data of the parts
RackR1 = RACK_42

## Sheet RACK_SUS_C7_C8.SchDoc: REMOTE RACK SUS-C7 & SUS-C8
size C; Engineer: L. Sanchez; Organization: LIGO Laboratory; Address1: California Institute of Technology; Address2: Massachusetts Institute of Technology; DocumentNumber: D1002740; Revision: v9; SheetNumber: 8; SheetTotal: 8
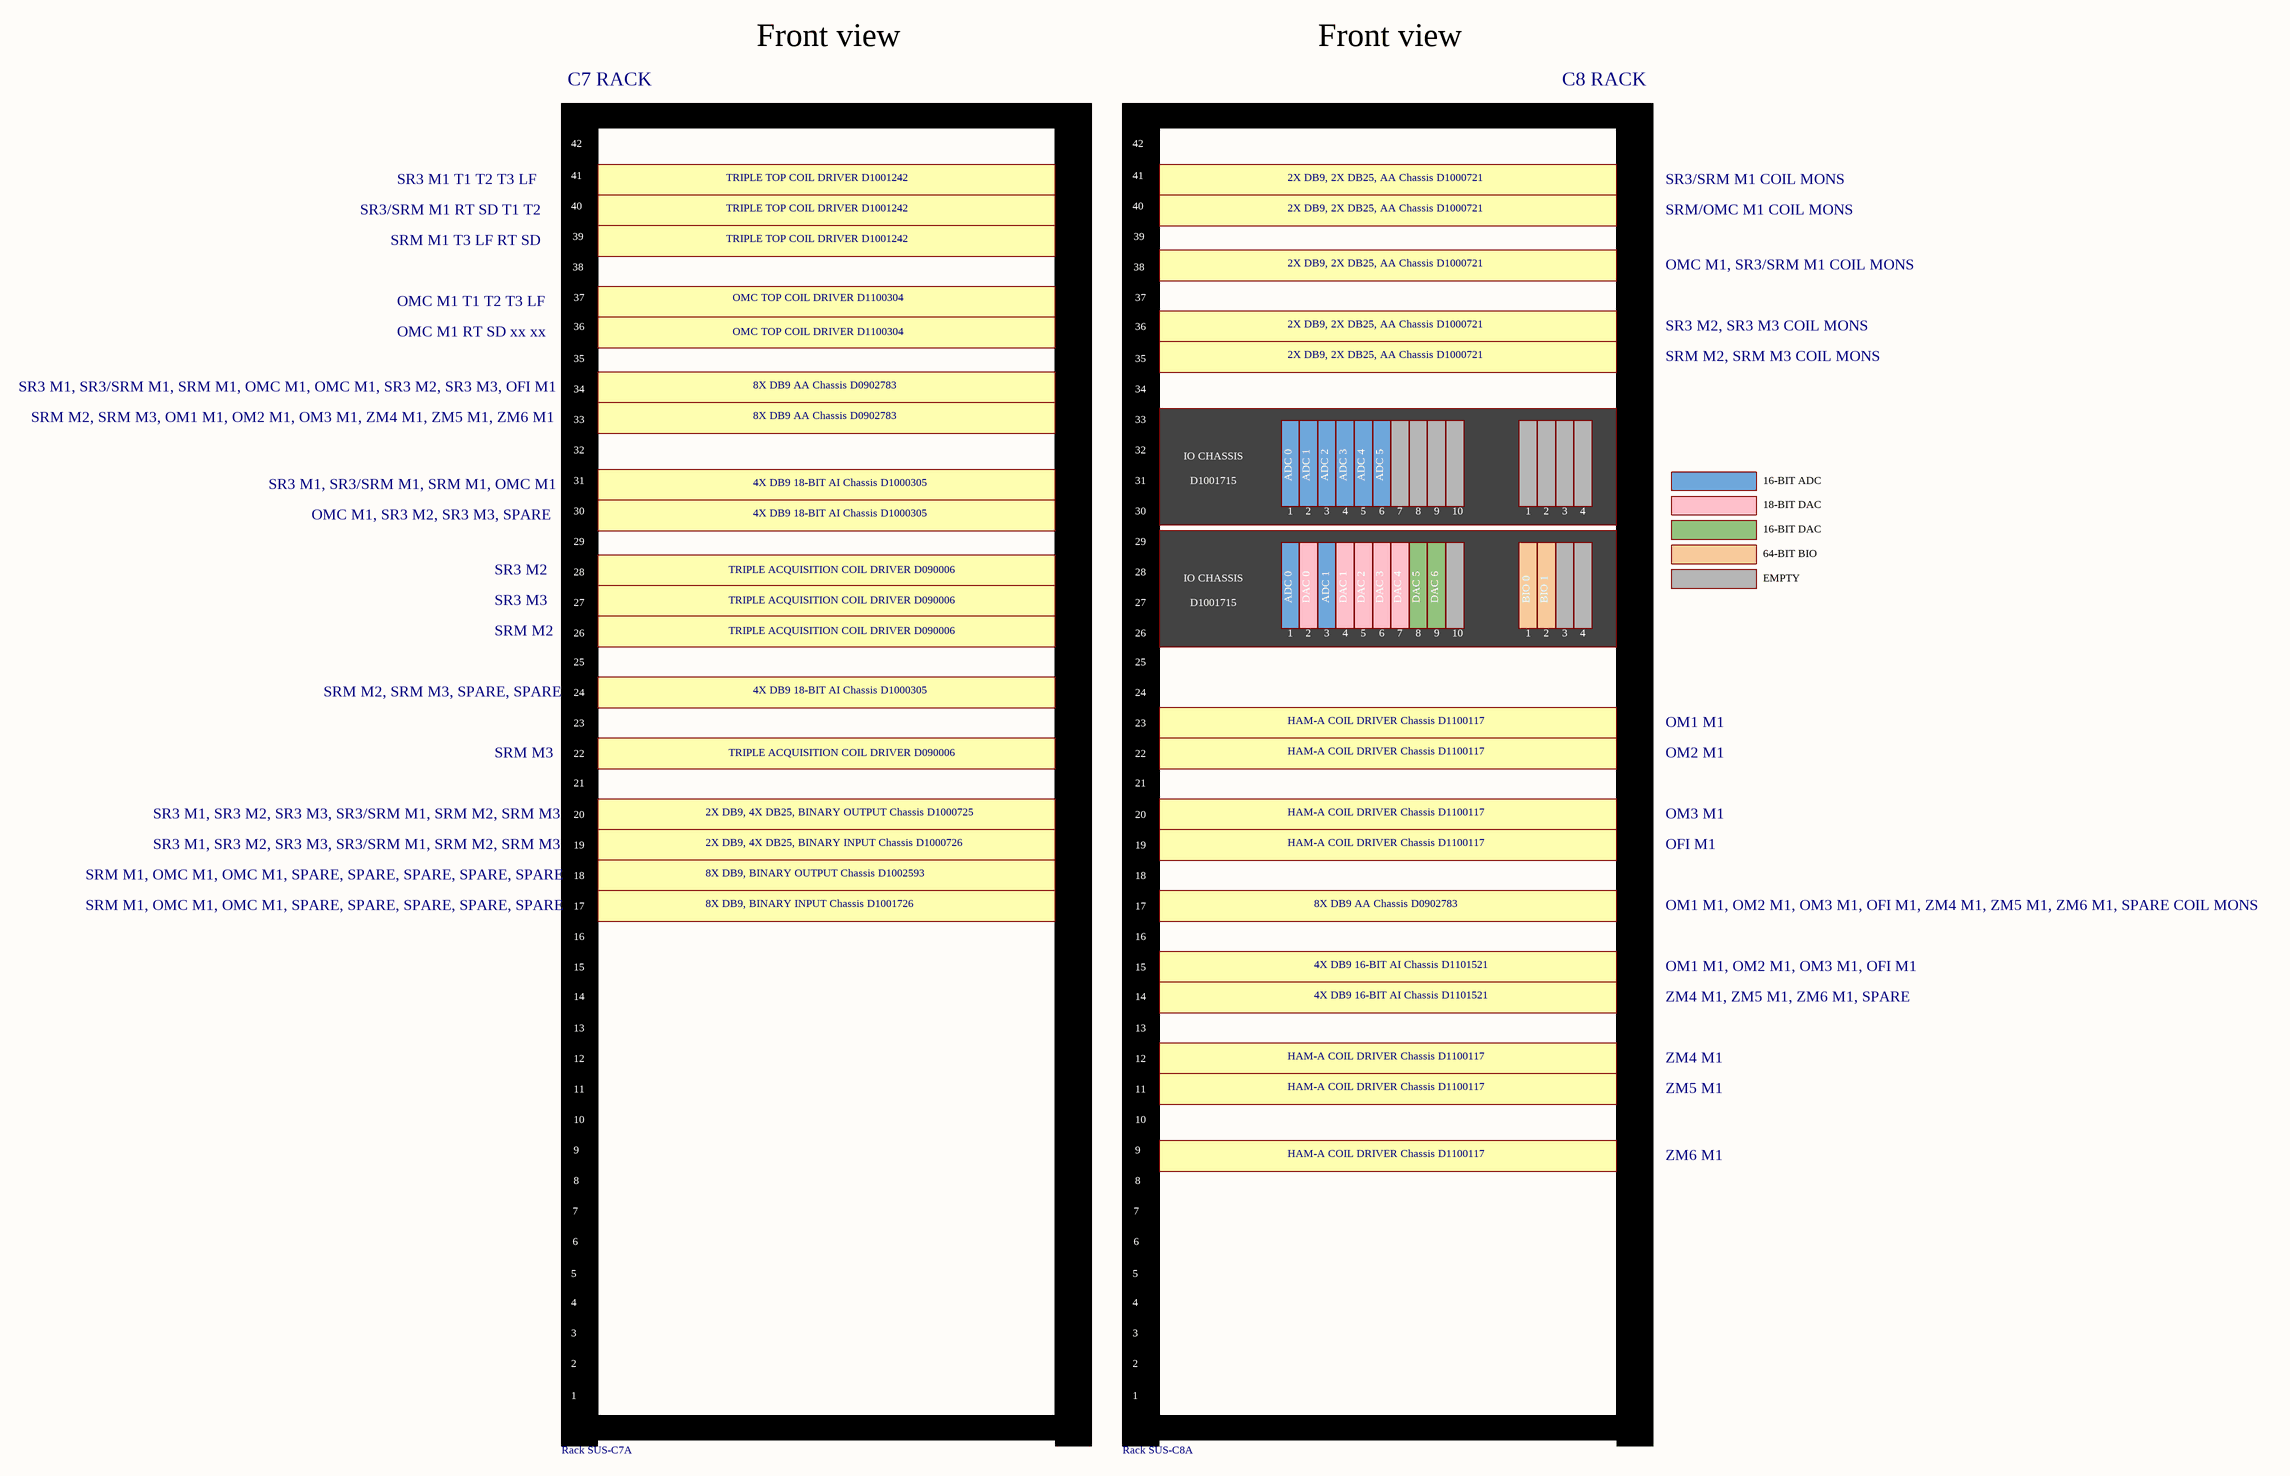
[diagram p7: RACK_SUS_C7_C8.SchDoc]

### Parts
Rack_SUS-C7  1U  Rack 42 pos  (value not drawn)  (part A of 2)
Rack_SUS-C8  1U  Rack 42 pos  (value not drawn)  (part A of 2)

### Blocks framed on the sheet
2X DB9, 4X DB25, BINARY OUTPUT Chassis D1000725: Rack_SUS-C7
HAM-A COIL DRIVER Chassis D1100117: Rack_SUS-C8

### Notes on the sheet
- Front view
- C7 RACK
- C8 RACK
- SR3 M1 T1 T2 T3 LF
- TRIPLE TOP COIL DRIVER D1001242
- 2X DB9, 2X DB25, AA Chassis D1000721
- SR3/SRM M1 COIL MONS
- SR3/SRM M1 RT SD T1 T2
- SRM M1 T3 LF RT SD
- SRM/OMC M1 COIL MONS
- OMC M1 T1 T2 T3 LF
- OMC TOP COIL DRIVER D1100304
- OMC M1, SR3/SRM M1 COIL MONS
- OMC M1 RT SD xx xx
- SR3 M2, SR3 M3 COIL MONS
- SRM M2, SRM M3 COIL MONS
- SR3 M1, SR3/SRM M1, SRM M1, OMC M1, OMC M1, SR3 M2, SR3 M3, OFI M1
- SRM M2, SRM M3, OM1 M1, OM2 M1, OM3 M1, ZM4 M1, ZM5 M1, ZM6 M1
- 8X DB9 AA Chassis D0902783
- SR3 M1, SR3/SRM M1, SRM M1, OMC M1
- 4X DB9 18-BIT AI Chassis D1000305
- IO CHASSIS
- D1001715
- ADC 0
- ADC 1
- ADC 2
- ADC 3
- ADC 4
- ADC 5
- 16-BIT ADC
- OMC M1, SR3 M2, SR3 M3, SPARE
- 1
- 2
- 3
- 4
- 5
- 6
- 7
- 8
- 9
- 10
- 18-BIT DAC
- 16-BIT DAC
- 64-BIT BIO
- SR3 M2
- SR3 M3
- TRIPLE ACQUISITION COIL DRIVER D090006
- DAC 0
- DAC 1
- DAC 2
- DAC 3
- DAC 4
- DAC 5
- DAC 6
- BIO 0
- BIO 1
- EMPTY
- SRM M2
- SRM M2, SRM M3, SPARE, SPARE
- HAM-A COIL DRIVER Chassis D1100117
- OM1 M1
- SRM M3
- OM2 M1
- SR3 M1, SR3 M2, SR3 M3, SR3/SRM M1, SRM M2, SRM M3
- (near Rack_SUS-C7) 2X DB9, 4X DB25, BINARY INPUT Chassis D1000726
- (near Rack_SUS-C8) HAM-A COIL DRIVER Chassis D1100117
- OM3 M1
- OFI M1
- SRM M1, OMC M1, OMC M1, SPARE, SPARE, SPARE, SPARE, SPARE
- 8X DB9, BINARY OUTPUT Chassis D1002593
- 8X DB9, BINARY INPUT Chassis D1001726
- OM1 M1, OM2 M1, OM3 M1, OFI M1, ZM4 M1, ZM5 M1, ZM6 M1, SPARE COIL MONS
- 4X DB9 16-BIT AI Chassis D1101521
- OM1 M1, OM2 M1, OM3 M1, OFI M1
- ZM4 M1, ZM5 M1, ZM6 M1, SPARE
- ZM4 M1
- ZM5 M1
- ZM6 M1

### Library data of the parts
Rack_SUS-C7 Rack_SUS-C8 = RACK_42

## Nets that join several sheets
ISC_127: HAM6_OUT_SUS (C16.D9F), SUSH56_ADC_DAC (C52.D9M)
ISC_128: HAM6_OUT_SUS (C16.D9F), SUSH56_ADC_DAC (C52.D9M)
ISC_129: HAM6_OUT_SUS (C102.D9F), SUSH56_ADC_DAC (C52.D9M)
ISC_186: HAM6_OUT_SUS (C7.D9F), SUSAUXH56_ADC_DAC (C51.D9M)
ISC_187: HAM6_OUT_SUS (C93.D9F), SUSAUXH56_ADC_DAC (C51.D9M)
ISC_188: HAM6_OUT_SUS (C98.D9F), SUSAUXH56_ADC_DAC (C51.D9M)
ISC_189: HAM6_OUT_SUS (C7.D9M), SUSH56_ADC_DAC (C60.D9F)
ISC_190: HAM6_OUT_SUS (C93.D9M), SUSH56_ADC_DAC (C60.D9F)
ISC_191: HAM6_OUT_SUS (C98.D9M), SUSH56_ADC_DAC (C60.D9F)
SUS_HAM5_043: HAM5_SR3 (C69.D37F), SUSH56_ADC_DAC (C27.D9M)
SUS_HAM5_044: HAM5_SR3 (C69.D37M), SUSH56_ADC_DAC (C34.D9F)
SUS_HAM5_045: HAM5_SR3 (C11.D37F), SUSH56_ADC_DAC (C27.D9M)
SUS_HAM5_046: HAM5_SR3 (C11.D37M), SUSH56_ADC_DAC (C34.D9F)
SUS_HAM5_047: HAM5_SRM (C15.D37F), SUSH56_ADC_DAC (C41.D9F)
SUS_HAM5_048: HAM5_SRM (C15.D37M), SUSH56_ADC_DAC (C43.D9F)
SUS_HAM5_052: HAM6_OUT_SUS (C92.D37M), SUSH56_ADC_DAC (C43.D9F)
SUS_HAM5_055: HAM5_SR3 (C75.D25F), SUSH56_ADC_DAC (C27.D25M)
SUS_HAM5_056: HAM5_SR3 (C75.D25M), SUSH56_ADC_DAC (C34.D25F)
SUS_HAM5_057: HAM5_SR3 (C81.D25F), SUSH56_ADC_DAC (C27.D25M)
SUS_HAM5_058: HAM5_SR3 (C81.D25M), SUSH56_ADC_DAC (C34.D25F)
SUS_HAM5_059: HAM5_SRM (C26.D25F), SUSH56_ADC_DAC (C27.D25M)
SUS_HAM5_060: HAM5_SRM (C26.D25M), SUSH56_ADC_DAC (C34.D25F)
SUS_HAM5_061: HAM5_SRM (C63.D25F), SUSH56_ADC_DAC (C27.D25M)
SUS_HAM5_062: HAM5_SRM (C63.D25M), SUSH56_ADC_DAC (C34.D25F)
SUS_HAM5_071: HAM5_SR3 (C69.D9F), SUSH56_ADC_DAC (C35.D9M)
SUS_HAM5_072: HAM5_SR3 (C11.D9F), SUSH56_ADC_DAC (C35.D9M)
SUS_HAM5_073: HAM5_SRM (C15.D9F), SUSH56_ADC_DAC (C35.D9M)
SUS_HAM5_077: HAM5_SR3 (C75.D9F), SUSH56_ADC_DAC (C35.D9M)
SUS_HAM5_081: HAM5_SR3 (C81.D9F), SUSH56_ADC_DAC (C35.D9M)
SUS_HAM5_082: HAM5_SRM (C26.D9F), SUSH56_ADC_DAC (C52.D9M)
SUS_HAM5_083: HAM5_SRM (C63.D9F), SUSH56_ADC_DAC (C52.D9M)
SUS_HAM5_091: HAM5_SR3 (C69.D9M), SUSH56_ADC_DAC (C19.D9F)
SUS_HAM5_092: HAM5_SR3 (C11.D9M), SUSH56_ADC_DAC (C19.D9F)
SUS_HAM5_093: HAM5_SRM (C15.D9M), SUSH56_ADC_DAC (C19.D9F)
SUS_HAM5_100: HAM5_SR3 (C75.D9M), SUSH56_ADC_DAC (C55.D9F)
SUS_HAM5_101: HAM5_SR3 (C81.D9M), SUSH56_ADC_DAC (C55.D9F)
SUS_HAM5_105: HAM5_SRM (C26.D9M), SUSH56_ADC_DAC (C58.D9F)
SUS_HAM5_106: HAM5_SRM (C63.D9M), SUSH56_ADC_DAC (C58.D9F)
SUS_HAM5_119: HAM5_SR3 (C69.D9F), SUSAUXH56_ADC_DAC (C38.D9M)
SUS_HAM5_120: HAM5_SR3 (C11.D9F), SUSAUXH56_ADC_DAC (C38.D9M)
SUS_HAM5_121: HAM5_SR3 (C69.D25M), SUSAUXH56_ADC_DAC (C38.D25M)
SUS_HAM5_122: HAM5_SR3 (C11.D25M), SUSAUXH56_ADC_DAC (C45.D25M)
SUS_HAM5_125: HAM5_SRM (C15.D9F), SUSAUXH56_ADC_DAC (C40.D9M)
SUS_HAM5_127: HAM5_SRM (C15.D25M), SUSAUXH56_ADC_DAC (C40.D25M)
SUS_HAM5_137: HAM5_SR3 (C75.D9F), SUSAUXH56_ADC_DAC (C47.D9M)
SUS_HAM5_138: HAM5_SR3 (C81.D9F), SUSAUXH56_ADC_DAC (C47.D9M)
SUS_HAM5_139: HAM5_SR3 (C75.D25M), SUSAUXH56_ADC_DAC (C47.D25M)
SUS_HAM5_140: HAM5_SR3 (C81.D25M), SUSAUXH56_ADC_DAC (C47.D25M)
SUS_HAM5_143: HAM5_SRM (C26.D9F), SUSAUXH56_ADC_DAC (C49.D9M)
SUS_HAM5_144: HAM5_SRM (C63.D9F), SUSAUXH56_ADC_DAC (C49.D9M)
SUS_HAM5_145: HAM5_SRM (C26.D25M), SUSAUXH56_ADC_DAC (C49.D25M)
SUS_HAM5_146: HAM5_SRM (C63.D25M), SUSAUXH56_ADC_DAC (C49.D25M)
SUS_HAM5_151C: HAM5_SR3 (C3.MicroD9), HAM5_SRM (C1.D9F)
SUS_HAM5_151D: HAM5_SR3 (C3.MicroD9), HAM5_SRM (C1.D9F)
SUS_HAM6_049: HAM6_OUT_SUS (C87.D37F), SUSH56_ADC_DAC (C41.D9F)
SUS_HAM6_050: HAM6_OUT_SUS (C87.D37M), SUSH56_ADC_DAC (C43.D9F)
SUS_HAM6_051: HAM6_OUT_SUS (C92.D37F), SUSH56_ADC_DAC (C41.D9F)
SUS_HAM6_074: HAM6_OUT_SUS (C87.D9F), SUSH56_ADC_DAC (C35.D9M)
SUS_HAM6_075: HAM6_OUT_SUS (C92.D9F), SUSH56_ADC_DAC (C35.D9M)
SUS_HAM6_094: HAM6_OUT_SUS (C87.D9M), SUSH56_ADC_DAC (C19.D9F)
SUS_HAM6_098: HAM6_OUT_SUS (C92.D9M), SUSH56_ADC_DAC (C55.D9F)
SUS_HAM6_126: HAM6_OUT_SUS (C87.D9F), SUSAUXH56_ADC_DAC (C40.D9M)
SUS_HAM6_128: HAM6_OUT_SUS (C87.D25M), SUSAUXH56_ADC_DAC (C40.D25M)
SUS_HAM6_131: HAM6_OUT_SUS (C92.D9F), SUSAUXH56_ADC_DAC (C45.D9M)
SUS_HAM6_133: HAM6_OUT_SUS (C92.D25M), SUSAUXH56_ADC_DAC (C45.D25M)
SUS_SQ_30: HAM5_OFI_ZM6 (C104.D25M), HAM6_OUT_SUS (C102.D25F)
SUS_SQ_031: HAM5_OFI_ZM6 (C100.D15F), HAM6_OUT_SUS (C102.D9M)
SUS_SQ_032: HAM6_OUT_SUS (C102.D9F), SUSH56_ADC_DAC (C35.D9M)
SUS_SQ_33: HAM5_OFI_ZM6 (C100.D9M), SUSH56_ADC_DAC (C60.D9F)
SUS_SQ_34: HAM5_OFI_ZM6 (C100.D9F), SUSAUXH56_ADC_DAC (C51.D9M)
SUS_ZM6_25: HAM5_OFI_ZM6 (C110.D9F), SUSH56_ADC_DAC (C52.D9M)
SUS_ZM6_28: HAM5_OFI_ZM6 (C111.D9M), SUSH56_ADC_DAC (C62.D9F)
SUS_ZM6_29: HAM5_OFI_ZM6 (C111.D9F), SUSAUXH56_ADC_DAC (C51.D9M)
